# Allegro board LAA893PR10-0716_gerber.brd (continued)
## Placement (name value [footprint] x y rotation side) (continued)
PJP13  PAD-OPEN1x2m  [JUMP_43X79]  239.19 61.34 90 top
PJP14  PAD-OPEN1x1m  [JUMP_43X39]  261.57 66.97 180 top
PJP15  PAD-OPEN1x1m  [JUMP_43X39]  269.97 39.03 180 top
PJP16  PAD-OPEN1x1m  [JUMP_43X39]  247.71 19.89 90 top
PJP18  PAD-OPEN1x3m  [JUMP_43X118]  196.83 47.73 180 top
PJP19  PAD-OPEN1x1m  [JUMP_43X39]  224.6 64.42 0 top
PJP20  PAD-OPEN1x1m  [JUMP_43X39]  238.82 54.66 180 top
PJP21  PAD-OPEN1x3m  [JUMP_43X118]  221.54 38.42 90 top
PJP22  PAD-OPEN1x3m  [JUMP_43X118]  214.85 33.83 0 top
PJP23  PAD-OPEN1x1m  [JUMP_43X39]  153.84 80.74 270 top
PJP26  PAD-OPEN1x2m  [JUMP_43X79]  277.88 24.87 0 top
PJP29  PAD-OPEN1x1m  [JUMP_43X39]  104.14 90.41 180 top
PJP35  PAD-OPEN1x1m  [JUMP_43X39]  164.23 81.29 0 top
PJP36  PAD-OPEN1x3m  [JUMP_43X118]  156.89 86.17 270 top
PJP100  PAD-OPEN 1x3m  [JUMP_43X118]  214.89 63.04 0 bottom
PJP101  PAD-OPEN 1x3m  [JUMP_43X118]  208.38 44.96 270 top
PJP102  PAD-OPEN 1x3m  [JUMP_43X118]  227.72 49.7 0 top
PJP200  PAD-OPEN 1x2m~D  [JUMP_43X79]  60.09 23.35 0 top
PJP201  PAD-OPEN1x1m  [JUMP_43X39]  72.07 15.9 90 top
PJP202  PAD-OPEN1x1m  [JUMP_43X39]  70.98 14.07 0 bottom
PJP203  JUMP_1x3m  [JUMP_43X118]  85.02 27.39 0 top
PJP204  JUMP_1x3m  [JUMP_43X118]  85.02 22.18 0 top
PJP300  -  [JUMP_43X118]  202.8 49.24 270 bottom
PJP302  PAD-OPEN 1x2m~D  [JUMP_43X79]  209.51 64.33 90 bottom
PJP400  PAD-OPEN1x1m  [JUMP_43X39]  115.96 77.06 180 bottom
PJP401  PAD-OPEN1x1m  [JUMP_43X39]  107.69 77.01 180 bottom
PJP500  PAD-OPEN 4x4m  [JUMP_43X118-NPM]  94.64 51.92 0 bottom
PJP700  PAD-OPEN 4x4m  [JUMP_43X118-NPM]  69.14 78.86 315 bottom
PJP701  PAD-OPEN1x1m  [JUMP_43X39]  77.4 82.47 270 top
PJPDC1  ACES_50290-0050N-001  [ACES_50290-0050N-001_5P-T]  56.65 92.65 90 bottom
PL1  FBMJ4516HS720NT_2P  [TAIYO_FBMJ4516HS720NT_2P]  60.84 8.99 180 top
PL2  FBMJ4516HS720NT_2P  [TAIYO_FBMJ4516HS720NT_2P]  60.84 11.72 180 top
PL3  BLM15AG102SN1D_2P  [MURAT_BLM15AG102SN1D_2P]  61.43 104.74 270 top
PL4  FBMJ4516HS720NT_2P  [TAIYO_FBMJ4516HS720NT_2P]  63.02 103.99 0 bottom
PL100  1UH +-20% 6.6A 5X5X3 MOLDING  [L_5X5X3_M_2P-NPM]  213.26 63.04 0 bottom
PL101  2.2UH +-20% 7.8A 7X7X3 MOLDING  [PANAS_ETQP3W2R2WFN_2P]  228.37 56.62 0 bottom
PL102  3.3UH +-20% 6.3A 7X7X3 MOLDING  [PANAS_ETQP3W2R2WFN_2P]  215.04 56.62 0 bottom
PL200  1UH +-20% 11A 7X7X3 MOLDING  [PANAS_ETQP3W2R2WFN_2P]  70.99 20.55 0 bottom
PL301  0.68UH +-20% 7.9A 5X5X3 MOLDING  [L_5X5X3_M_2P]  202.93 57.2 270 bottom
PL500  0.15UH_ETQP4LR15AFM_29A_20%  [PANAS_ETQP4LR15AFM_4P]  115.48 50.34 180 bottom
PL501  FBMA-L11-453215800LMA90T_2P  [KC_FBMA-L11-453215800LMA90T_2P]  93.29 51.92 0 bottom
PL700  1UH +-20% 6.6A 5X5X3 MOLDING  [L_5X5X3_M_2P]  71.07 76.93 135 bottom
PL701  3.3UH +-20% PIMB104T-3R3MS 10A  [TOKO_FDVE1040-H-3R3M-P3_2P]  83.75 71.42 180 bottom
PQ2  -  [FDV301N-G_SOT23-3]  68.88 102.81 180 top
PQ3  -  [MMST3904-7-F_SOT323-3]  72.4 102.47 180 top
PQ100  -  [SIS412DN-T1-GE3_POWERPAK8-5]  223.8 57.67 90 top
PQ101  -  [SIS412DN-T1-GE3_POWERPAK8-5]  213.11 59.65 270 top
PQ102  -  [SI7716ADN-T1-GE3_POWERPAK8-5]  222.44 55.84 270 top
PQ103  -  [SI7716ADN-T1-GE3_POWERPAK8-5]  215.99 53.92 90 top
PQ200  -  [SIS412DN-T1-GE3_POWERPAK8-5]  66.7 22.03 0 top
PQ201  -  [SI7716ADN-T1-GE3_POWERPAK8-5]  64.92 20.46 270 top
PQ701  -  [SI4835DDY-T1-E3_SO8]  92.49 76.68 0 bottom
PQ705  -  [AON6970_DFN5X6D-8-7]  68.13 75.32 270 top
PQ708  -  [DCX124EK-7-F_SC74R-6]  68.97 95.81 270 top
PQ709  SIS496EDNT-T1-GE3 1N POWERPAK1212-8  [SI7716ADN-T1-GE3_POWERPAK8-5]  64.15 95.73 0 top
PQ710  -  [SI7716ADN-T1-GE3_POWERPAK8-5]  66.37 93.88 270 top
PQ711  -  [DMN65D8LW-7_SOT323-3]  73.27 90.17 270 top
PR1  1K_0402_5%  [R_0402]  291.64 8.13 270 top
PR2  100K_0402_5%  [R_0402]  51.52 9.8 270 top
PR7  0_0402_5%  [R_0402]  74.27 103.23 270 bottom
PR8  2.2K_0402_5%  [R_0402]  73.31 100.08 90 bottom
PR9  33_0402_5%  [R_0402]  74.27 100.99 270 bottom
PR10  100K_0402_1%  [R_0402]  73.31 102.31 90 bottom
PR11  10K_0402_1%  [R_0402]  66.38 102.76 270 top
PR12  15K_0402_1%  [R_0402]  72.37 103.24 270 bottom
PR16  4.7K_0805_5%  [R_0805]  66.69 105.77 90 bottom
PR100  6.49K_0402_1%  [R_0402]  219 45.5 90 top
PR101  15K_0402_1%  [R_0402]  217.6 46.41 270 top
PR102  10K_0402_1%  [R_0402]  219.88 45.5 90 top
PR103  0_0402_5%  [R0402_0OHM]  219.06 44.93 90 bottom
PR104  10K_0402_1%  [R_0402]  216.71 46.41 270 top
PR105  20K_0402_1%  [R_0402]  220.77 45.5 90 top
PR106  16.9K_0402_1%  [R_0402]  215.82 45.5 90 top
PR107  100K_0402_1%  [R_0402]  222.61 47.02 90 top
PR108  0_0402_5%  [R0402_0OHM]  221.66 47.02 90 top
PR109  2.2_0603_5%  [R_0603]  214.75 50.59 180 top
PR110  2.2_0603_5%  [R_0603]  223.38 50.59 180 top
PR111  4.7_1206_5%  [R_1206]  227.14 54.01 90 top
PR112  4.7_1206_5%  [R_1206]  210.17 58.97 270 top
PR113  0_0402_5%  [R0402_0OHM]  213.59 46.02 0 top
PR114  200_0402_1%  [R_0402]  214.94 48.18 180 top
PR200  2.2_0603_5%  [R_0603]  67.24 15.66 270 bottom
PR201  19.6K_0402_1%  [R_0402]  65.66 9.61 90 top
PR202  5.1_0603_5%  [R_0603]  64.07 8.48 0 top
PR203  4.7_1206_5%  [R_1206]  67.56 16.61 180 top
PR204  0_0603_5%  [R0603_0OHM]  62.79 8.99 270 top
PR205  8.06K_0402_1%  [R_0402]  71.93 8.03 90 bottom
PR206  768K_0402_1%  [R_0402]  65.77 7.4 0 bottom
PR207  0_0402_5%  [R0402_0OHM]  69.87 8.1 270 top
PR209  10K_0402_1%  [R_0402]  71.03 7.16 0 bottom
PR210  0_0402_5%  [R0402_0OHM]  71.51 8.99 180 top
PR303  1M_0402_1%  [R_0402]  206.74 59.56 0 top
PR305  4.7_1206_5%  [R_1206]  203.95 57 180 top
PR306  0_0402_5%  [R_0402]  207.58 63.29 180 top
PR307  7.5K_0402_1%  [R_0402]  206.75 59.54 90 bottom
PR308  0_0402_5%  [R_0402]  206.66 62.4 0 top
PR309  1K_0402_5%  [R_0402]  208.94 60.57 90 bottom
PR310  10K_0402_1%  [R_0402]  206.66 61.51 0 bottom
PR312  0_0603_5%  [R0603_0OHM]  203.74 60.96 270 top
PR313  0_0402_5%  [R0402_0OHM]  205.23 59.7 90 top
PR315  100K_0402_1%  [R_0402]  207.66 60.45 180 top
PR400  100K_0402_5%  [R_0402]  116.52 73.07 180 bottom
PR401  47K_0402_5%  [R_0402]  115.62 72.17 270 bottom
PR402  8.66K_0402_1%  [R_0402]  107.17 74.1 270 bottom
PR403  10K_0402_1%  [R_0402]  107.17 72.26 270 bottom
PR500  75_0402_1%  [R_0402]  106.6 62.14 90 bottom
PR501  365K_0402_1%  [R_0402]  103.49 62.2 90 bottom
PR502  75_0402_1%  [R_0402]  102.6 62.2 90 bottom
PR503  681K_0402_1%  [R_0402]  101.71 62.2 90 bottom
PR504  36.5K_0402_1%  [R_0402]  100.82 62.2 90 bottom
PR505  10K_0402_5%  [R_0402]  105.52 64.93 90 bottom
PR506  39K_0402_1%  [R_0402]  104.63 64.93 90 bottom
PR507  150K_0402_1%  [R_0402]  103.74 64.93 90 bottom
PR508  100K_0402_1%  [R_0402]  102.85 64.93 90 bottom
PR509  20K_0402_1%  [R_0402]  101.96 64.93 90 bottom
PR510  39K_0402_5%~N  [R_0402]  106.41 64.93 90 bottom
PR511  10K_0402_5%  [R_0402]  107.49 62.14 90 bottom
PR512  2.15K_0402_1%  [R_0402]  110.13 50.9 180 top
PR513  75_0402_1%  [R_0402]  100.14 65.7 180 top
PR514  20K_0402_1%  [R_0402]  110.14 51.84 0 top
PR515  3.01K_0402_1%  [R_0402]  110.14 52.79 0 top
PR516  1.91K_0402_1%  [R_0402]  100.14 67.51 180 top
PR517  2.2_0603_5%  [R_0603]  97.2 57.07 0 bottom
PR518  2M_0402_1%  [R_0402]  107.5 60.17 180 top
PR519  1_0603_5%  [R_0603]  100.12 68.56 180 top
PR520  0_0402_5%  [R0402_0OHM]  99.22 64.76 0 top
PR521  4.87K_0402_1%  [R_0402]  107.68 71.69 270 top
PR522  4.7_1206_5%  [R_1206]  103.93 52.75 270 bottom
PR523  10K_0402_5%  [R_0402]  109.53 70.66 180 top
PR524  2M_0402_1%  [R_0402]  105.65 59.22 90 top
PR525  27K_0402_1%  [R_0402]  106.59 59.22 0 top
PR526  10_0603_1%  [R_0603]  104 72.56 270 top
PR527  54.9_0402_1%  [R_0402]  101.52 72.75 270 top
PR528  75_0402_1%  [R_0402]  100.63 72.75 270 top
PR529  110_0402_1%  [R_0402]  99.74 72.75 270 top
PR531  0_0402_5%  [R0402_0OHM]  109.53 68.75 180 top
PR532  0_0402_5%  [R0402_0OHM]  109.53 67.86 180 top
PR534  0_0402_5%  [R0402_0OHM]  102.92 70.84 90 top
PR535  4.75K_0402_1%  [R_0402]  109.52 71.53 90 top
PR536  0_0402_5%  [R0402_0OHM]  100.14 63.88 180 top
PR539  0_0402_5%  [R0402_0OHM]  100.14 66.59 180 top
PR701  0.01_1206_1%  [R_1206_4P-D]  68.51 85.23 90 bottom
PR703  100_0402_1%  [R_0402]  78.69 90.25 180 bottom
PR704  0_0402_5%  [R0402_0OHM]  78.66 88.42 90 bottom
PR705  0_0402_5%  [R0402_0OHM]  77.77 88.42 90 bottom
PR708  10_1206_5%  [R_1206]  74.33 88.08 270 bottom
PR709  1M_0402_1%  [R_0402]  73.53 92.28 0 top
PR710  34K_0402_1%  [R_0402]  80.58 87.36 180 top
PR711  6.49K_0402_1%  [R_0402]  80.57 85.78 270 top
PR712  2.2_0603_5%  [R_0603]  74.6 82.6 180 bottom
PR713  100K_0402_1%  [R_0402]  77.71 77.7 0 bottom
PR714  0_0402_5%  [R0402_0OHM]  80.12 88.45 270 bottom
PR715  154K_0402_1%  [R_0402]  81.79 80.99 90 top
PR716  0_0402_5%  [R0402_0OHM]  81.07 88.45 270 bottom
PR717  0_0402_5%  [R0402_0OHM]  84.66 83.16 180 bottom
PR718  0_0402_5%  [R0402_0OHM]  84.66 84.94 180 bottom
PR720  0_0402_5%  [R0402_0OHM]  84.66 84.05 180 bottom
PR721  0.01_1206_1%  [R_1206_4P-D]  88.25 69.05 180 top
PR722  4.02K_0402_1%  [R_0402]  79.88 78.66 270 bottom
PR723  10_0603_1%  [R_0603]  81.02 78.66 270 bottom
PR725  1K_0402_5%  [R_0402]  77.71 78.65 0 bottom
PR726  4.7_1206_5%  [R_1206]  72.73 77.3 180 top
PR728  0_0402_5%  [R0402_0OHM]  82.31 77.9 90 bottom
PR729  154K_0402_1%  [R_0402]  80.83 80.99 90 top
PR730  4.02K_0402_1%  [R_0402]  72.55 96.61 0 top
PR731  4.02K_0402_1%  [R_0402]  74.36 97.52 270 top
PR737  4.7_0402_1%  [R_0402]  67.62 95.49 90 top
PR788  20K_0402_1%  [R_0402]  82.42 82.96 0 top
PR799  10K_0402_1%  [R_0402]  76.82 78.61 270 bottom
PRP2  100_0804_8P4R_5%  [RP_0804_8P4R]  53.03 7.72 90 top
PT1  PAD~D  [TPC12]  263.14 34.9 180 bottom
PT2  PAD~D  [TPC12]  261.38 35.29 180 bottom
PU100  -  [TPS51285BRUKR_QFN20_3X3]  217.48 48.03 0 top
PU200  -  [RT8207MZQW_WQFN20_3X3]  69.16 11.39 270 bottom
PU300  SYX198DQNC QFN 10P PWM  [SY8208DQNC_QFN10_3X3]  205.3 60.01 90 bottom
PU400  -  [APL5930KAI-TRG_SO8]  108.84 71.29 90 bottom
PU500  TPS51624RSM QFN 32P VCORE IC  [TPS51622RSM_QFN32_4X4]  102.51 68.43 270 top
PU501  -  [CSD97374CQ4M_SON8_3P5X4P5]  103.71 57.59 270 bottom
PU700  BQ24777RUYR WQFN 28P CHARGER  [BQ24715URUYR_WQFN28_4X4]  78.43 85.21 270 bottom
QA1  -  [L2N7002WT1G_SC-70-3]  38.4 23.73 90 top
QA2  -  [DMN66D0LDW-7_SOT363-6]  27.23 26.92 270 top
QC1  -  [DMN66D0LDW-7_SOT363-6]  187.45 52.62 270 top
QD1  -  [L2N7002WT1G_SC-70-3]  151.84 22.82 0 top
QE2  -  [DMN66D0LDW-7_SOT363-6]  250.68 46.92 90 top
QE3  MMBT3904WT1G_SC70-3~D  [MMBT3904WT1G_SC70-3]  148.35 62.58 270 top
QE4  MMBT3904WT1G_SC70-3~D  [MMBT3904WT1G_SC70-3]  251.32 35.97 180 top
QE5  MMBT3904WT1G_SC70-3~D  [MMBT3904WT1G_SC70-3]  152.13 21.44 270 bottom
QE6  MMBT3904WT1G_SC70-3~D  [MMBT3904WT1G_SC70-3]  101.49 46.25 270 top
QE7  MMBT3904WT1G_SC70-3~D  [MMBT3904WT1G_SC70-3]  237.44 37.93 270 bottom
QL1  -  [DMN66D0LDW-7_SOT363-6]  281.15 80.82 0 top
QL2  -  [DMN66D0LDW-7_SOT363-6]  282.45 79.67 180 top
QN1  -  [DMN66D0LDW-7_SOT363-6]  277.18 10.14 180 bottom
QV1  -  [AO6405_TSOP6]  109.77 94.01 90 bottom
QV2  -  [L2N7002WT1G_SC-70-3]  109.1 98.07 90 bottom
QV7  -  [L2N7002WT1G_SC-70-3]  117.47 80.68 90 top
QV8  -  [LP2301ALT1G_SOT23-3]  118.79 86.3 180 top
QV501  -  [L2N7002WT1G_SC-70-3]  286.32 79.16 0 bottom
QV502  -  [L2N7002WT1G_SC-70-3]  281.79 77.01 270 bottom
QZ1  -  [LP2301ALT1G_SOT23-3]  112.54 86.21 270 top
QZ2  -  [DMN66D0LDW-7_SOT363-6]  242.35 35.8 0 top
QZ3  -  [DMN66D0LDW-7_SOT363-6]  271.61 19.1 270 top
QZ4  -  [DDTA114EUA-7-F_SOT323-3]  275.69 18.71 0 top
QZ6  -  [SI3456DDV-T1-GE3_TSOP6]  166.03 85.9 180 top
QZ7  -  [DMN66D0LDW-7_SOT363-6]  288.59 81.12 90 top
QZ9  -  [DDTA114EUA-7-F_SOT323-3]  284.73 79.6 0 top
QZ10  -  [DMN66D0LDW-7_SOT363-6]  145.52 88.12 270 top
RA1  10K_0402_5%  [R_0402]  20.58 15.7 180 bottom
RA2  100K_0402_5%  [R_0402]  21.69 17.64 270 bottom
RA3  0_0603_5%  [R0603_0OHM]  30.17 12.19 0 top
RA4  0_0603_5%  [R0603_0OHM]  27.43 8.74 90 top
RA5  2.2K_0402_5%  [R_0402]  27.34 19.18 270 top
RA6  2.2K_0402_5%  [R_0402]  26.02 17.37 90 top
RA7  24.9_0402_1%  [R_0402]  24.04 13.17 180 top
RA8  24.9_0402_1%  [R_0402]  24.04 15.86 180 top
RA9  33_0402_5%  [R_0402]  42.14 18.9 180 top
RA12  1K_0402_5%  [R_0402]  40.74 22.02 0 top
RA13  1K_0402_5%  [R_0402]  40.74 21.06 0 top
RA14  33_0402_5%  [R_0402]  38.9 13.95 0 top
RA17  33_0402_5%  [R_0402]  39 17.06 0 top
RA18  10K_0402_5%  [R_0402]  38.91 12.1 90 top
RA21  100K_0402_5%  [R_0402]  30.21 27.05 270 top
RA24  4.7K_0402_5%  [R_0402]  23.12 14.06 0 top
RA25  4.7K_0402_5%  [R_0402]  23.12 14.97 0 top
RA35  0_0402_5%  [R0402_0OHM]  32.81 20.8 0 bottom
RA36  0_0402_5%  [R0402_0OHM]  28.53 11.16 270 bottom
RA37  0_0402_5%  [R0402_0OHM]  33.26 27.09 0 bottom
RA39  0_0805_5%  [R0805_0OHM]  37.03 8.94 180 top
RA40  33_0402_5%  [R_0402]  39.85 13.07 0 top
RA44  100K_0402_5%  [R_0402]  31.52 23.11 90 top
RA45  0_0402_5%  [R0402_0OHM]  30.59 23.11 90 top
RC1  330K_0402_5%  [R_0402]  169.66 45.88 90 bottom
RC2  1K_0402_5%  [R_0402]  290.17 10.6 270 bottom
RC4  0_0402_5%  [R0402_0OHM]  181.18 45.58 0 bottom
RC7  10M_0402_5%  [R_0402]  183.08 45.58 0 bottom
RC8  20K_0402_5%  [R_0402]  186.76 45.83 270 bottom
RC9  1M_0402_5%  [R_0402]  172.07 45.88 90 bottom
RC10  20K_0402_5%  [R_0402]  185.81 45.83 270 bottom
RC11  1K_0402_5%  [R_0402]  165.8 43.71 90 top
RC14  51_0402_5%  [R_0402]  139.86 60.88 0 top
RC15  51_0402_5%  [R_0402]  139.86 63.55 0 top
RC16  51_0402_5%  [R_0402]  139.86 62.66 0 top
RC17  3.01K_0402_1%  [R_0402]  159.88 80.11 90 bottom
RC18  1K_0402_1%  [R_0402]  139.86 61.77 0 top
RC19  33_0402_5%  [R_0402]  154.97 40.49 0 bottom
RC20  33_0402_5%  [R_0402]  154.97 41.57 0 bottom
RC21  51_0402_5%  [R_0402]  127.48 58.4 0 bottom
RC22  33_0402_5%  [R_0402]  154.97 38.59 0 bottom
RC23  33_0402_5%  [R_0402]  154.97 39.54 0 bottom
RC25  1K_0402_5%  [R_0402]  128.63 82.73 270 bottom
RC26  0_0402_5%  [R0402_0OHM]  193.85 51.85 90 top
RC27  0_0402_5%  [R_0402]  194.82 51.85 90 top
RC29  1K_0402_5%  [R_0402]  189.73 64.24 180 top
RC31  1K_0402_5%  [R_0402]  188.72 59.48 180 top
RC33  499_0402_1%  [R_0402]  180.06 59.29 0 bottom
RC34  499_0402_1%  [R_0402]  180.06 58.4 0 bottom
RC35  0_0402_5%  [R0402_0OHM]  188.83 66.99 270 bottom
RC38  33_0402_5%  [R_0402]  188.83 63.98 90 bottom
RC50  0_0402_5%  [R0402_0OHM]  187.94 54.46 0 bottom
RC55  33_0402_5%  [R_0402]  187.94 53 0 bottom
RC61  33_0402_5%  [R_0402]  195.89 59.33 270 bottom
RC62  33_0402_5%  [R_0402]  195.89 63.7 90 bottom
RC63  1M_0402_5%  [R_0402]  154.81 81.01 180 bottom
RC65  0_0402_5%  [R0402_0OHM]  155.17 80.06 0 bottom
RC66  10K_0402_5%  [R_0402]  178.49 62.55 180 top
RC67  22_0402_5%  [R_0402]  161.68 42.89 0 top
RC68  10K_0402_5%  [R_0402]  174.98 66.46 180 bottom
RC69  3.01K_0402_1%  [R_0402]  152.26 80.04 90 bottom
RC74  22_0402_5%  [R_0402]  160.83 42.89 180 top
RC77  0_0402_5%  [R0402_0OHM]  186.53 73.53 270 top
RC78  330K_0402_5%  [R_0402]  171.12 46.79 270 bottom
RC79  10K_0402_5%  [R_0402]  171.24 45.88 90 top
RC80  8.2K_0402_5%  [R_0402]  184.72 75.04 180 top
RC81  10K_0402_5%  [R_0402]  176.96 58.97 180 top
RC82  10K_0402_5%  [R_0402]  176.96 59.85 180 top
RC88  0_0402_5%  [R0402_0OHM]  191.18 74.6 180 top
RC89  0_0402_5%  [R0402_0OHM]  191.18 73.45 180 top
RC91  10K_0402_5%  [R_0402]  167.07 46.08 90 top
RC92  10K_0402_5%  [R_0402]  175.85 46.29 0 top
RC95  8.2K_0402_5%  [R_0402]  186.56 75.04 180 top
RC98  0_0402_5%  [R_0402]  93.53 58.08 180 bottom
RC99  0_0402_5%  [R_0402]  93.53 56.18 180 bottom
RC102  1K_0402_5%  [R_0402]  76.01 52.11 270 top
RC103  1K_0402_5%  [R_0402]  75.09 51.19 90 top
RC106  1K_0402_5%  [R_0402]  87.12 50.02 180 top
RC109  0_0402_5%  [R_0402]  86.79 57.78 270 bottom
RC112  0_0402_5%  [R_0402]  92.62 59.99 0 bottom
RC113  1K_0402_5%  [R_0402]  86.27 46.08 0 top
RC114  49.9_0402_1%  [R_0402]  127.63 68.34 90 bottom
RC115  0_0402_5%  [R_0402]  92.62 59.04 0 bottom
RC116  62_0402_5%  [R_0402]  125.79 68.33 180 bottom
RC117  51_0402_5%  [R_0402]  87.12 47.23 180 top
RC118  0_0402_5%  [R_0402]  92.62 57.13 0 bottom
RC119  0_0402_5%  [R_0402]  75.92 45.88 90 top
RC120  1K_0402_5%  [R_0402]  75.93 47.71 180 top
RC121  56_0402_5%  [R_0402]  124.88 69.58 0 bottom
RC122  1K_0402_5%  [R_0402]  87.12 48.18 180 top
RC123  10K_0402_5%  [R_0402]  131.02 77.99 0 bottom
RC124  51_0402_5%  [R_0402]  127.56 80.96 270 bottom
RC125  51_0402_5%  [R_0402]  127.56 82.2 90 bottom
RC126  51_0402_5%  [R_0402]  126.6 82.2 90 bottom
RC127  51_0402_5%  [R_0402]  126.6 80.96 270 bottom
RC128  51_0402_5%  [R_0402]  75.92 43.97 90 top
RC129  51_0402_5%  [R_0402]  86.79 59.68 270 bottom
RC130  200_0402_1%  [R_0402]  129.98 46.96 270 top
RC131  121_0402_1%  [R_0402]  130.87 46.96 270 top
RC132  100_0402_1%  [R_0402]  129.09 46.96 270 top
RC133  24.9_0402_1%  [R_0402]  158.02 68.57 180 top
RC136  0_0402_5%  [R_0402]  174.85 61.34 0 top
RC139  100K_0402_5%  [R_0402]  167.88 78.99 270 top
RC140  1K_0402_5%  [R_0402]  177.39 65.89 0 top
RC141  100K_0402_5%  [R_0402]  171.18 81.02 270 bottom
RC142  100K_0402_5%  [R_0402]  166.62 81 270 bottom
RC149  3.01K_0402_1%  [R_0402]  151.38 80.06 180 bottom
RC152  22.6_0402_1%  [R_0402]  161.21 56.42 90 top
RC153  10K_0402_5%  [R_0402]  174.99 46.22 270 top
RC155  100K_0402_5%  [R_0402]  176.93 63.08 0 bottom
RC156  100K_0402_5%  [R_0402]  176.08 65.89 180 top
RC158  100K_0402_5%  [R_0402]  174.94 68.9 180 bottom
RC160  100K_0402_5%  [R_0402]  174.94 68.02 180 bottom
RC161  0_0402_5%  [R0402_0OHM]  128.63 80.96 270 bottom
RC163  10K_0402_5%  [R_0402]  170.9 79.01 270 top
RC164  20K_0402_5%  [R_0402]  172.79 79 270 top
RC171  10K_0402_5%  [R_0402]  175.15 63.08 0 bottom
RC174  100K_0402_5%  [R_0402]  183.93 54.08 0 top
RC175  100K_0402_5%  [R_0402]  183.93 53.14 0 top
RC176  1K_0402_5%  [R_0402]  169.9 79 270 top
RC178  49.9_0402_1%  [R_0402]  164.21 46.98 270 bottom
RC179  1K_0402_5%  [R_0402]  178.49 61.34 180 top
RC180  1K_0402_5%  [R_0402]  178.49 63.44 180 top
RC183  1K_0402_1%  [R_0402]  128.39 60.88 180 bottom
RC184  1K_0402_1%  [R_0402]  128.39 61.77 180 bottom
RC185  49.9_0402_1%  [R_0402]  126.55 62.25 90 bottom
RC186  8.2K_0402_1%  [R_0402]  158.92 81.02 270 bottom
RC187  49.9_0402_1%  [R_0402]  163.32 46.98 270 bottom
RC188  1K_0402_1%  [R_0402]  128.39 62.66 180 bottom
RC189  1K_0402_1%  [R_0402]  128.39 64.43 180 bottom
RC190  1K_0402_1%  [R_0402]  128.39 63.55 180 bottom
RC191  1K_0402_5%  [R_0402]  122.67 46.86 270 top
RC192  0_0402_5%  [R_0402]  169.22 80.11 0 bottom
RC193  0_0402_5%  [R_0402]  129.92 78.08 270 bottom
RC194  0_0402_5%  [R_0402]  175.92 46.98 180 bottom
RC195  0_0402_5%  [R_0402]  129.65 46.96 0 bottom
RC196  0_0603_5%  [R_0603]  131.24 80.12 90 bottom
RC197  150_0402_5%  [R_0402]  125.69 80.06 0 top
RC198  10K_0402_5%  [R_0402]  127.45 80.06 0 top
RC199  10K_0402_5%  [R_0402]  129.97 82.73 270 bottom
RC201  1.5K_0402_5%  [R_0402]  129.97 80.96 270 bottom
RC202  1K_0402_5%  [R_0402]  140.07 86.91 0 top
RC204  75_0402_1%  [R_0402]  126.68 68.35 270 bottom
RC207  43_0402_5%  [R_0402]  128.64 66.55 180 bottom
RC208  110_0402_1%  [R_0402]  128.62 68.34 270 bottom
RC209  100_0402_1%  [R_0402]  130.81 77.96 180 top
RC211  5.11_0402_1%  [R_0402]  158.35 58.46 0 top
RC212  0_0402_5%  [R0402_0OHM]  172.12 45.87 90 top
RC213  0_0402_5%  [R_0402]  174.09 45.3 90 top
RC216  0_0402_5%  [R_0402]  174.09 43.42 0 top
RC217  0_0402_5%  [R0402_0OHM]  174.09 44.37 0 top
RC218  100_0402_1%  [R_0402]  129.03 77.96 180 top
RC224  0_0402_5%  [R_0402]  179.75 81.02 270 top
RC225  0_0402_5%  [R_0402]  180.77 81.02 270 top
RC226  0_0402_5%  [R_0402]  181.78 81.02 270 top
RC227  0_0402_5%  [R_0402]  182.8 81.02 270 top
RC228  0_0402_5%  [R_0402]  183.82 81.02 270 top
RC229  0_0402_5%  [R_0402]  184.83 81.02 270 top
RC230  0_0402_5%  [R_0402]  185.85 81.02 270 top
RC231  0_0402_5%  [R_0402]  186.86 80.11 90 top
RC240  10K_0402_5%  [R_0402]  146.59 80.4 90 bottom
RC241  10K_0402_5%  [R_0402]  147.48 80.4 90 bottom
RC242  10K_0402_5%  [R_0402]  164.83 46.98 270 top
RC243  10K_0402_5%  [R_0402]  165.78 46.98 270 top
RC245  100K_0402_5%  [R_0402]  170.35 46.79 270 top
RC247  10K_0402_5%  [R_0402]  184.85 52.22 180 top
RC300  10K_0402_5%  [R_0402]  161.57 63.74 0 top
RC301  0_0402_5%  [R_0402]  288.74 10.17 90 bottom
RC302  1K_0402_5%  [R_0402]  183.91 52.23 270 bottom
RC303  1K_0402_5%  [R_0402]  184.85 51.32 90 bottom
RC304  100K_0402_5%  [R_0402]  189.38 74.6 180 top
RC305  1K_0402_5%  [R_0402]  76.05 55.82 180 top
RC306  10K_0402_5%  [R_0402]  171.83 78.09 90 top
RD2  470_0402_5%  [R_0402]  91.15 9.45 90 top
RD4  1.8K_0402_1%  [R_0402]  80.45 15.29 180 top
RD5  2_0402_1%  [R_0402]  79.54 16.24 0 top
RD6  1.8K_0402_1%  [R_0402]  78.61 17.19 180 top
RD7  24.9_0402_1%  [R_0402]  79.94 18.06 90 top
RD9  220K_0402_5%  [R_0402]  149.97 20.67 90 top
RD10  66.5_0402_1%  [R_0402]  118.68 10.62 180 top
RD11  66.5_0402_1%  [R_0402]  118.68 9.74 180 top
RD12  66.5_0402_1%  [R_0402]  200.6 8.09 180 top
RD13  66.5_0402_1%  [R_0402]  200.6 7.2 180 top
RD14  2M_0402_5%  [R_0402]  149.02 20.67 90 top
RD15  0_0402_5%  [R0402_0OHM]  140.38 16.38 270 top
RD16  0_0402_5%  [R0402_0OHM]  139.43 16.38 270 top
RD18  1.8K_0402_1%  [R_0402]  198.6 13.06 0 top
RD19  2_0402_1%  [R_0402]  200.44 13.06 0 top
RD20  1.8K_0402_1%  [R_0402]  200.06 12.17 0 top
RD21  24.9_0402_1%  [R_0402]  203.2 12.11 180 top
RD22  1.8K_0402_1%  [R_0402]  160.91 18.27 180 top
RD23  2_0402_1%  [R_0402]  159 18.27 180 top
RD24  1.8K_0402_1%  [R_0402]  159.99 17.32 0 top
RD25  24.9_0402_1%  [R_0402]  159 16.36 180 top
RD27  0_0402_5%  [R0402_0OHM]  222.1 17.09 270 top
RD28  0_0402_5%  [R0402_0OHM]  220.09 18.91 270 top
RE8  100K_0402_5%  [R_0402]  254.89 59.65 90 top
RE11  100K_0402_5%  [R_0402]  252.41 59.65 90 top
RE20  100K_0402_5%  [R_0402]  114.87 96.25 180 bottom
RE21  10K_0402_5%  [R_0402]  253.43 59.65 90 top
RE24  10K_0402_5%  [R_0402]  252.92 70.57 90 top
RE25  100K_0402_5%  [R_0402]  250.68 54.86 0 top
RE26  10_0402_5%  [R_0402]  250.68 55.75 0 top
RE31  100K_0402_5%  [R_0402]  267.78 53.7 270 top
RE32  0_0402_5%  [R0402_0OHM]  267.78 51.76 270 top
RE33  10K_0402_5%  [R_0402]  266.89 52.79 90 top
RE35  10K_0402_5%  [R_0402]  253.97 32.5 270 top
RE36  100K_0402_5%  [R_0402]  257.79 53.21 270 top
RE37  2.2K_0402_5%  [R_0402]  267.9 40.39 180 top
RE43  2.2K_0402_5%  [R_0402]  267.9 41.28 180 top
RE48  10K_0402_5%  [R_0402]  248.71 41.16 90 top
RE51  10K_0402_5%  [R_0402]  247.14 45.62 270 top
RE55  100K_0402_5%  [R_0402]  249.79 41.16 90 top
RE56  10K_0402_5%  [R_0402]  255.18 34.18 0 top
RE57  1K_0402_5%  [R_0402]  270.1 43.16 0 top
RE58  100K_0402_5%  [R_0402]  269.16 43.17 270 top
RE60  43_0402_5%  [R_0402]  264.02 34.79 270 top
RE61  0_0402_5%  [R0402_0OHM]  266.81 46.73 270 top
RE63  100K_0402_5%  [R_0402]  256.08 29.77 90 top
RE64  4.7K_0402_5%  [R_0402]  270.1 42.21 0 top
RE65  100_0402_1%  [R_0402]  258.34 30.1 0 top
RE66  10_0402_5%  [R_0402]  251.34 39.09 180 top
RE67  10K_0402_5%  [R_0402]  249.36 49.43 0 top
RE68  100K_0402_5%  [R_0402]  247.79 48.49 270 top
RE69  8.2K_0402_5%  [R_0402]  250.42 37.19 0 top
RE70  2.2K_0402_5%  [R_0402]  249.44 36.3 0 top
RE71  49.9_0402_1%  [R_0402]  300.35 41.43 180 top
RE72  10K_0402_5%  [R_0402]  300.87 37.5 180 top
RE73  10K_0402_5%  [R_0402]  300.87 35.28 180 top
RE75  100K_0402_5%  [R_0402]  300.87 36.36 180 top
RE77  1.58K_0402_1%  [R_0402]  251.33 44.88 180 top
RE78  1K_0402_5%  [R_0402]  251.33 40.11 180 top
RE79  1K_0402_5%  [R_0402]  258.75 53.21 270 top
RE81  10K_0402_5%  [R_0402]  266.86 49.11 270 top
RE82  10K_0402_5%  [R_0402]  267.75 49.11 270 top
RE83  100K_0402_5%  [R_0402]  261.27 65.26 180 top
RE84  100K_0402_5%  [R_0402]  256.83 60.58 270 top
RE86  10K_0402_5%  [R_0402]  258.32 33.81 90 top
RE87  10K_0402_5%  [R_0402]  254.44 71.49 270 top
RE88  47K_0402_5%  [R_0402]  260.16 32.88 90 top
RE91  0_0402_5%  [R_0402]  256.98 54.97 180 top
RE100  0_0402_5%  [R0402_0OHM]  251.58 51 90 top
RE101  0_0402_5%  [R0402_0OHM]  250.68 51 90 top
RE274  0_0402_5%  [R_0402]  184.83 51.29 180 top
RE275  0_0402_5%  [R0402_0OHM]  255.84 59.66 90 top
RE278  0_0402_5%  [R_0402]  251.65 48.21 90 top
RE279  0_0402_5%  [R0402_0OHM]  170.34 43.15 0 top
RE280  0_0402_5%  [R_0402]  170.36 45.04 270 top
RE281  0_0402_5%  [R_0402]  167.07 44.63 270 top
RE282  0_0402_5%  [R0402_0OHM]  168.08 44.63 270 top
RE283  0_0402_5%  [R_0402]  263.1 49.19 90 bottom
RI13  10K_0402_5%  [R_0402]  288.59 38.86 0 top
RI14  22.1K_0402_1%  [R_0402]  284.57 41.88 270 top
RL1  10K_0402_5%  [R_0402]  262.57 87.02 180 top
RL2  10K_0402_5%  [R_0402]  262.57 88.91 180 top
RL3  0_0402_5%  [R0402_0OHM]  254.35 86.13 180 bottom
RL4  4.7K_0402_5%  [R_0402]  253.22 91.17 90 top
RL5  10K_0402_5%  [R_0402]  251.08 92.09 270 top
RL6  4.7K_0402_5%  [R_0402]  252.11 92.09 270 top
RL7  0_0402_5%  [R0402_0OHM]  252.12 90.25 180 top
RL8  0_0603_5%  [R0603_0OHM]  249.97 92.04 270 top
RL9  10K_0402_5%  [R_0402]  252.11 89.33 180 top
RL10  0_0402_5%  [R0402_0OHM]  249.02 84.44 0 top
RL11  1M_0402_5%  [R_0402]  250.87 84.45 270 top
RL12  1K_0402_5%  [R_0402]  261.66 85.91 0 top
RL13  3.01K_0402_1%  [R_0402]  251.82 82.61 270 top
RL14  150_0402_5%  [R_0402]  283 83.79 90 top
RL15  75_0402_1%  [R_0402]  267.99 90.18 90 top
RL16  75_0402_1%  [R_0402]  269.26 90.18 90 top
RL17  75_0402_1%  [R_0402]  275.61 90.18 90 top
RL18  75_0402_1%  [R_0402]  276.88 90.18 90 top
RL19  150_0402_5%  [R_0402]  283.89 83.79 90 top
RL20  150_0402_5%  [R_0402]  284.78 83.79 90 top
RL21  5.6_0603_5%  [R_0603]  252.59 80.44 270 top
RL22  5.6_0603_5%  [R_0603]  253.79 80.44 270 top
RL23  5.6_0603_5%  [R_0603]  255.06 80.44 270 top
RL24  5.6_0603_5%  [R_0603]  256.27 80.44 270 top
RL25  5.6_0603_5%  [R_0603]  257.54 80.44 270 top
RL26  5.6_0603_5%  [R_0603]  258.75 80.44 270 top
RL27  5.6_0603_5%  [R_0603]  260.02 80.44 270 top
RL28  5.6_0603_5%  [R_0603]  261.22 80.44 270 top
RL29  1M_0402_5%  [R_0402]  279.92 80.73 90 top
RL30  1M_0402_5%  [R_0402]  279.92 79.69 270 top
RN1  100K_0402_5%  [R_0402]  272.32 10.08 0 bottom
RN2  100K_0402_5%  [R_0402]  276.53 14.03 270 bottom
RN3  2.2K_0402_5%  [R_0402]  279.05 4.36 0 bottom
RN4  2.2K_0402_5%  [R_0402]  281.81 4.36 180 bottom
RN5  10K_0402_5%  [R_0402]  268.33 10.98 270 bottom
RN6  10K_0402_5%  [R_0402]  250.14 19.09 270 top
RN7  10K_0402_5%  [R_0402]  251.04 18.17 270 top
RN8  4.7K_0402_5%  [R_0402]  260.36 16.31 180 top
RN9  4.7K_0402_5%  [R_0402]  259.45 17.2 0 top
RN10  4.7K_0402_5%  [R_0402]  260.36 18.97 180 top
RN11  4.7K_0402_5%  [R_0402]  259.45 18.08 0 top
RN12  4.7K_0402_5%  [R_0402]  267.7 17.94 0 top
RN13  4.7K_0402_5%  [R_0402]  268.62 17.06 180 top
RN14  4.7K_0402_5%  [R_0402]  268.62 19.79 180 top
RN16  4.7K_0402_5%  [R_0402]  268.62 18.9 180 top
RN18  4.7K_0402_5%  [R_0402]  259.45 19.86 0 top
RN19  7.87K_0402_1%  [R_0402]  259.45 20.76 0 top
RN20  4.7K_0402_5%  [R_0402]  268.62 15.28 180 top
RN21  4.7K_0402_5%  [R_0402]  268.62 16.17 180 top
RN22  4.7K_0402_5%  [R_0402]  259.62 11.26 0 top
RN23  4.7K_0402_5%  [R_0402]  262.3 11.27 180 top
RN24  4.7K_0402_5%  [R_0402]  269.99 20.66 270 top
RN25  4.7K_0402_5%  [R_0402]  269.99 18.87 270 top
RPC1  10K_8P4R_5%  [RP_0804_8P4R]  176.31 43.85 90 top
RPC2  2.2K_0804_8P4R_5%  [RP_0804_8P4R]  165.2 80.56 90 bottom
RPC3  10K_8P4R_5%  [RP_0804_8P4R]  180.13 68.93 0 top
RPC4  10K_8P4R_5%  [RP_0804_8P4R]  177.8 67.42 180 top
RPC5  10K_8P4R_5%  [RP_0804_8P4R]  185.28 58.86 180 top
RPC6  10K_8P4R_5%  [RP_0804_8P4R]  179.94 64.38 0 bottom
RPC7  10K_8P4R_5%  [RP_0804_8P4R]  184.39 58.26 180 bottom
RPC8  10K_8P4R_5%  [RP_0804_8P4R]  179.94 67.18 0 bottom
RPC9  10K_8P4R_5%  [RP_0804_8P4R]  181.28 64.57 180 top
RPC10  10K_8P4R_5%  [RP_0804_8P4R]  185.28 55.94 180 top
RPC11  33_0804_8P4R_5%  [RP_0804_8P4R]  187.81 62.14 0 top
RPC12  33_0804_8P4R_5%  [RP_0804_8P4R]  187.81 56.23 0 top
RPC14  2.2K_0804_8P4R_5%  [RP_0804_8P4R]  183.24 60 0 bottom
RPC15  10K_8P4R_5%  [RP_0804_8P4R]  180.32 63.08 0 top
RPC16  10K_8P4R_5%  [RP_0804_8P4R]  184.14 67.43 180 top
RPC17  10K_8P4R_5%  [RP_0804_8P4R]  177.91 68.68 180 bottom
RPC18  10K_8P4R_5%  [RP_0804_8P4R]  177.91 65.88 180 bottom
RPC19  10K_8P4R_5%  [RP_0804_8P4R]  177.6 58.85 0 bottom
RPC20  100K_0804_8P4R_5%  [RP_0804_8P4R]  169.48 82.02 90 bottom
RPE3  2.2K_0804_8P4R_5%  [RP_0804_8P4R]  260.35 51.73 90 top
RPE5  100K_0804_8P4R_5%  [RP_0804_8P4R]  263.27 51.73 90 top
RPE6  10K_8P4R_5%  [RP_0804_8P4R]  262.73 34.15 270 top
RPE7  10K_8P4R_5%  [RP_0804_8P4R]  299.85 40.15 0 top
RPE9  100K_0804_8P4R_5%  [RP_0804_8P4R]  256.68 70.96 90 top
RPE10  100K_0804_8P4R_5%  [RP_0804_8P4R]  253.56 52.18 90 top
RR1  10_0402_5%  [R_0402]  283.89 35.97 90 top
RR2  191_0402_1%  [R_0402]  278.56 32.74 0 top
RR3  0_0402_5%  [R0402_0OHM]  282.57 35.97 90 top
RR4  0_0402_5%  [R0402_0OHM]  281.68 35.97 90 top
RR5  4.7K_0402_1%  [R_0402]  289.7 28.26 0 top
RR6  100K_0402_5%  [R_0402]  283.16 24.15 90 top
RR8  100K_0402_5%  [R_0402]  284.1 25.07 270 top
RR11  1M_0402_5%  [R_0402]  275.46 27.08 270 top
RR15  10K_0402_5%  [R_0402]  281.8 26.33 0 top
RV1  4.7K_0402_5%  [R_0402]  109.98 89.39 180 top
RV2  4.7K_0402_5%  [R_0402]  107.22 89.39 0 top
RV3  100K_0402_5%  [R_0402]  100.54 93.52 270 top
RV4  270K_0402_5%  [R_0402]  112.1 98.14 180 bottom
RV5  47K_0402_5%  [R_0402]  110.25 97.24 90 bottom
RV6  47K_0402_5%  [R_0402]  118.37 82.46 180 top
RV7  2.2K_0402_5%  [R_0402]  223.78 95.61 180 top
RV8  10K_0402_5%  [R_0402]  219.44 94.52 90 top
RV9  2.2K_0402_5%  [R_0402]  220.96 95.61 0 top
RV50  4.99K_0402_1%  [R_0402]  221.64 84.73 180 bottom
RV51  4.7K_0402_5%  [R_0402]  232.88 85.18 180 bottom
RV52  4.7K_0402_5%  [R_0402]  231.97 86.09 0 bottom
RV54  4.7K_0402_5%  [R_0402]  222.45 88.12 270 bottom
RV55  4.7K_0402_5%  [R_0402]  220.69 81.7 0 top
RV56  4.7K_0402_5%  [R_0402]  220.68 80.76 0 top
RV57  4.7K_0402_5%  [R_0402]  233.47 79.12 180 bottom
RV58  4.7K_0402_5%  [R_0402]  226.41 75.77 90 top
RV60  4.7K_0402_5%  [R_0402]  228.81 75.77 90 top
RV61  4.7K_0402_5%  [R_0402]  223.39 87.22 90 bottom
RV62  4.7K_0402_5%  [R_0402]  222.83 81.7 0 top
RV63  4.7K_0402_5%  [R_0402]  232.56 80.02 0 bottom
RV64  4.7K_0402_5%  [R_0402]  222.83 80.5 0 top
RV65  4.7K_0402_5%  [R_0402]  226.42 78.02 90 top
RV66  4.7K_0402_5%  [R_0402]  228.82 78.02 90 top
RV67  1M_0402_5%  [R_0402]  230.79 88.12 270 bottom
RV68  100K_0402_5%  [R_0402]  225.21 75.77 90 top
RV501  100K_0402_5%  [R_0402]  287.33 73.08 270 bottom
RV502  100K_0402_5%  [R_0402]  287.33 70.38 90 bottom
RV503  5.1M_0402_5%  [R_0402]  286.43 76.03 0 bottom
RV504  1M_0402_5%  [R_0402]  287.35 76.92 180 bottom
RV505  100K_0402_5%  [R_0402]  286.43 77.94 0 bottom
RV507  100K_0402_5%  [R_0402]  279.56 74.47 0 bottom
RV510  4.7K_0402_5%  [R_0402]  231.97 83.35 0 bottom
RV511  4.7K_0402_5%  [R_0402]  232.88 84.24 180 bottom
RV514  100K_0402_5%  [R_0402]  233.47 77.11 180 bottom
RV515  100K_0402_5%  [R_0402]  233.47 78.24 180 bottom
RZ5  100K_0402_5%  [R_0402]  144.44 87.76 270 top
RZ8  2.2K_0402_5%  [R_0402]  251.51 13.37 0 top
RZ9  2.2K_0402_5%  [R_0402]  254.26 13.37 180 top
RZ10  1M_0402_5%  [R_0402]  259.43 13.31 180 top
RZ14  100K_0402_5%  [R_0402]  241.59 34.72 0 top
RZ15  100K_0402_5%  [R_0402]  244.34 34.72 180 top
RZ16  100K_0402_5%  [R_0402]  148.54 88.25 270 top
RZ17  0_0402_5%  [R0402_0OHM]  197.94 87.25 270 top
RZ18  4.7K_0402_5%  [R_0402]  247.7 22 90 top
RZ19  4.7K_0402_5%  [R_0402]  246.81 22 90 top
RZ21  33_0402_5%  [R_0402]  269.12 37.3 0 top
RZ22  10K_0402_5%  [R_0402]  267.98 34.55 180 top
RZ24  10K_0402_5%  [R_0402]  272.53 24.35 90 top
RZ25  390_0402_5%  [R_0402]  271.26 16.31 270 top
RZ26  33_0402_5%  [R_0402]  199.72 87.25 270 top
RZ27  110_0402_1%  [R_0402]  275.5 17.5 0 top
RZ28  330_0402_5%  [R_0402]  270.3 16.31 270 top
RZ29  33_0402_5%  [R_0402]  197.05 87.25 270 top
RZ30  33_0402_5%  [R_0402]  194.5 87.22 270 top
RZ31  100K_0402_5%  [R_0402]  288.6 79.99 180 top
RZ32  150_0402_5%  [R_0402]  287.46 83.45 0 top
RZ33  110_0402_1%  [R_0402]  284.78 78.4 0 top
RZ34  110_0402_1%  [R_0402]  285.62 82.4 180 top
RZ35  33_0402_5%  [R_0402]  198.83 87.25 270 top
RZ38  100K_0402_5%  [R_0402]  251.29 30.85 180 top
RZ41  0_0402_5%  [R_0402]  221.47 68.9 90 top
RZ42  0_0402_5%  [R0402_0OHM]  222.4 68.9 90 top
RZ44  0.01_1206_1%  [R_1206]  200.11 43.13 270 top
RZ46  0_0603_5%  [R_0603]  224.6 62.17 0 top
RZ51  0_0402_5%  [R0402_0OHM]  265.88 31.48 180 top
RZ56  0_0402_5%  [R_0402]  244.28 32.33 0 top
RZ57  0_0402_5%  [R0402_0OHM]  245.2 31.43 180 top
SW1  SS3-CMFTQR9_3P  [SW_SS3-CMFTQR9_3P]  297.13 6.17 180 bottom
SW3  SKRBAAE010_4P  [SW_SKRBAAE010_4P]  294.16 86 270 top
T8  PAD~D  [TPC12]  169.35 46.58 0 top
T9  PAD~D  [TPC12]  253.15 35.69 90 top
T10  PAD~D  [TPC12]  129.12 71.03 180 bottom
T11  PAD~D  [TPC12]  127.75 70.66 180 bottom
T12  PAD~D  [TPC12]  135.7 68.21 0 top
T13  PAD~D  [TPC12]  128 72.71 180 bottom
T14  PAD~D  [TPC12]  133.8 66.93 0 top
T15  PAD~D  [TPC12]  132.42 69.19 0 top
T16  PAD~D  [TPC12]  173.77 60.69 0 top
T21  PAD~D  [TPC12]  168.37 57.61 0 top
T22  PAD~D  [TPC12]  169.49 62.48 0 top
T27  PAD~D  [TPC12]  173.61 57.7 180 bottom
T28  PAD~D  [TPC12]  128.36 47.43 180 bottom
T29  PAD~D  [TPC12]  128.79 49.22 180 bottom
T30  PAD~D  [TPC12]  128.98 74.45 180 bottom
T31  PAD~D  [TPC12]  128.99 75.95 180 bottom
T32  PAD~D  [TPC12]  249.86 61.49 0 top
T33  PAD~D  [TPC12]  140.82 76.35 180 bottom
T34  PAD~D  [TPC12]  141.89 77.27 180 bottom
T35  PAD~D  [TPC12]  129.87 66 180 bottom
T74  PAD~D  [TPC12]  128.51 65.35 180 bottom
T75  PAD~D  [TPC12]  126.26 65.07 180 bottom
T76  PAD~D  [TPC12]  135.53 66.36 0 top
T77  PAD~D  [TPC12]  134.11 65.48 0 top
T88  PAD~D  [TPC12]  260.75 86.54 180 top
T89  PAD~D  [TPC12]  261.96 87.97 180 top
T96  PAD~D  [TPC12]  254.37 72.72 180 top
T97  PAD~D  [TPC12]  250.97 71.28 180 top
T98  PAD~D  [TPC12]  249.3 65.66 180 top
T109  PAD~D  [TPC12]  168.97 77 0 top
TL1  NS692417  [MHPC_NS692417_24P]  279.42 81.51 180 bottom
UA1  -  [ALC3235-CG_MQFN48_6X6]  36.31 15.37 90 top
UC1  BDW-ULT-DDR3L_BGA1168  [BDW-ULT-DDR3L_BGA_1168P-T]  170.78 73.51 0 bottom
UC2  -  [W25Q64FVSSIQ_SO8]  190.61 68.5 0 bottom
UC3  -  [W25Q32FVSSIQ_SO8]  194.42 51.54 180 bottom
UC4  -  [74AHC1G09GW_TSSOP5]  185.23 73.58 180 top
UC5  TC7SH08FU_SSOP5~D  [TC7SH08FU_SSOP5]  187.81 71.46 0 top
UC6  TC7SH08FU_SSOP5~D  [TC7SH08FU_SSOP5]  190.78 52.63 270 top
UC7  -  [74CBTLV3126BQ_DHVQFN14_2P5X3]  90.03 59.31 270 bottom
UC8  -  [74AUP1G07GW_TSSOP5]  136.89 88.32 270 top
UD1  -  [74AUP1G07GW_TSSOP5]  146.15 19.79 0 top
UE2  -  [MEC5085-LZY_DQFN132_11X11]  262.69 47.91 180 top
UE3  ECE1099-FZG_QFN40_6X6~D  [ECE1099-FZG_QFN40_6X6]  251.21 68.01 270 top
UI1  SY6288D10CAC_MSOP8  [G547I2P81U_MSOP8]  91.7 84.21 270 bottom
UI2  SY6288D10CAC_MSOP8  [G547I2P81U_MSOP8]  255.09 92.9 270 bottom
UI3  -  [TPS2544RTER_WQFN16_3X3]  286.76 40.41 0 top
UL1  WGI218LM-QQ89-B0_QFN48_6X6~D  [WGI217LM-QPN9-A2_QFN48_6X6]  253.65 87.99 270 top
UL2  TC7SH08FU_SSOP5~D  [TC7SH08FU_SSOP5]  261.23 83.75 270 top
UN1  LNG3DMTR_LGA16_3X3~D  [LNG3DMTR_LGA16_3X3]  280.67 8.35 270 bottom
UN2  -  [PI3EQX6741STZDEX_TQFN20_4X4]  265.04 19.67 180 top
UN3  TPS22967DSGR_SON8_2X2~D  [TPS22965DSGR_SON8_2X2]  252.44 20.12 270 top
UR1  OZ777FJ2LN-B1_QFN48_6X6  [OZ777FJ2LN_QFN48_6X6]  281.67 33.11 270 top
UV2  -  [AP2330W-7_SC59-3]  225.01 93.76 90 bottom
UV7  -  [PS8339BQFN56GTR2-A0_QFN56_7X7]  229.22 78.23 180 bottom
UV24  -  [AP2821KTR-G1_SOT23-5]  101.79 88.81 90 top
UV501  AP2337SA-7 SOT-23  [AP2330W-7_SC59-3]  286.19 64.81 0 bottom
UV502  PI3C3125LEX_TSSOP14~D  [PI3C3125LEX_TSSOP14]  279.99 68.76 90 bottom
UZ1  AT97SC3205-X3A15-ABF_TSSOP28~D  [AT97SC3205_TSSOP28]  194.16 78.56 0 top
UZ2  APE8990GN3B_SON14_2X3  [TPS22966DPUR_SON14_2X3]  242.75 56.82 90 top
UZ3  TPS22967DSGR_SON8_2X2~D  [TPS22965DSGR_SON8_2X2]  248.73 29.3 90 top
UZ5  -  [RT9818A-44GU3_SC70-3]  268.83 36.32 270 top
UZ6  TC7SH08FU_SSOP5~D  [TC7SH08FU_SSOP5]  267.22 33.45 270 top
UZ8  APE8990GN3B_SON14_2X3  [TPS22966DPUR_SON14_2X3]  223.14 67.16 180 top
UZ9  APE8990GN3B_SON14_2X3  [TPS22966DPUR_SON14_2X3]  218.29 42.92 180 top
UZ10  TC7SH08FU_SSOP5~D  [TC7SH08FU_SSOP5]  264.03 58.72 180 top
UZ11  -  [TC7SH08FU_SSOP5]  247.5 33.8 180 top
YC1  32.768KHZ_12.5PF_9H03220008  [Y_9H03220008_2P]  182.07 48.49 0 bottom
YC2  24MHZ_12PF_X3G024000DC1H  [Y_X3G024000DC1H_4P]  155.67 82.28 180 bottom
YE1  32.768KHZ_12.5PF_Q13FC135000040  [Y_Q13FC135000040_2P]  269.35 44.39 90 top
YL1  25MHZ_18PF_7V25000034  [Y_7V25000034_4P]  249.49 80.48 90 top

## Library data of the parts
CA1-CA6 CA8 CA11-CA13 CA17 CA19 CA22-CA24 CA27 CA28 CA30 CA33 CA35 CA41 CA45 CA47 CA50 CA54 CC1-CC13 CC17 CC20-CC22 CC24-CC28 CC35 CC37 CC40 CC43 CC44 CC49 CC50 CC52 CC57-CC59 CC61 CC65 CC66 CC68-CC73 CC78 CC80 CC82 CC83 CC95-CC97 CC100 CD1-CD11 CD21-CD27 CD30-CD44 CD54-CD60 CD63 CD64 CE2 CE3 CE8 CE10-CE20 CE22-CE30 CE34-CE40 CE46 CI3-CI5 CI7 CI10 CI12 CI13 CI16 CI17 CI19 CI27 CI28 CL1-CL3 CL5 CL6 CL8-CL11 CL13-CL15 CL18 CL19 CN2-CN4 CN13-CN20 CN23-CN26 CN29 CN30 CR2-CR4 CR6 CR8 CR10 CR13 CR15 CR17 CR19 CR21-CR27 CR31 CR35 CV1-CV6 CV10 CV11 CV23 CV26 CV60-CV62 CV66 CV69 CV71-CV80 CV145-CV150 CV152 CV153 CV156 CV157 CV501-CV510 CV512-CV514 CZ1 CZ2 CZ4-CZ7 CZ9 CZ13-CZ18 CZ20-CZ23 CZ25 CZ30 CZ31 CZ34-CZ37 CZ39-CZ48 CZ50 CZ64 PC3 PC20 PC105 PC203 PC212-PC215 PC300 PC304 PC400 PC402 PC403 PC501-PC504 PC506 PC511-PC514 PC520 PC702 PC703 PC711 PC713 PC718 PC719 PC726-PC728 PC730 = C_0402
CA9 CA10 CA16 CA18 CA25 CA26 CA29 CA31 CA43 CA44 CA46 CA48 CA49 CA51-CA53 CC23 CC29-CC34 CC36 CC47 CC51 CC55 CC56 CC60 CC63 CC64 CC79 CC84 CC85 CD12-CD19 CD28 CD29 CD45-CD52 CD61 CD62 CE1 CE21 CE31 CE32 CI6 CI11 CL4 CL7 CL12 CL16 CL17 CL20 CL21 CN1 CR1 CR7 CR9 CR14 CR18 CR34 CV9 CV12 CV27 CZ19 CZ38 PC1 PC9 PC100 PC109-PC111 PC114 PC117-PC119 PC204 PC208 PC209 PC211 PC301 PC302 PC309 PC310 PC500 PC505 PC507-PC510 PC701 PC710 PC712 PC721 PC722 PC729 PC731 = C_0603
CC39 CD20 CD53 PC207 PC966 = C_D2
CC41 CC42 = C_D3
CC67 CC77 CC81 CI1 CI8 CI14 = C_1206
CL22 = C_1808
CMOS1 = SHORTPADS-S: User Part Number: PART#
DA1-DA3 DA6 DA7 = L03ESDL5V0CC3-2_SOT23-3
DA4 DA5 DE1 DZ1-DZ4 = RB751S40T1G_SOD523-2
DI1 DI4 DI6 = L05ESDL5V0NA-4_SLP2510P8-10-9
DI2 DI3 DI5 DV4 PD5 = AZC199-02SPR7G_SOT23-3
DV1-DV3 = BAT54CW_SOT323-3
FD1-FD4 = FIDUCIAL_C40M80
H1-H4 H6 H7 H9-H11 H13 H21 = H_2P3
H5 = H_5P5N
H12 = H_3P6
H14-H17 = H_3P5
H18 = H_5P2X2P6N
H19 = H_3P2
H22 = H_3P3
H23 = H_2P6N
JAPS1 = ACES_50506-01841-P01_18P
JDEG1 JLPDE1 = HB_A531015-SCHR21_10P
JDIMM1 = LCN_DAN06-K4406-0103_204P
JDIMM2 = LCN_DAN06-K4406-0103_204P-S
JEDP1 = ACES_50398-04041-001_40P
JFAN1 = ACES_50271-0040N-001_4P
JHDMI1 = CONCR_099BKAC19YBLCNF_19P-T
JHP1 = SINGA_2SJ3080-039111F_6P-T
JKBTP1 = E-T_6705K-Y16N-00L_16P
JLED1 = E-T_6705K-Y10N-00L_10P-T
JLOM1 = SANTA_130456-511_13P-T
JMDP1 = ACON_MAR2B-20K1803_20P-T
JNGFF1 = BELLW_80148-3221_67P-T
JRTC1 = TYCO_2-1775293-2_2P
JSATA1 = STARC_115B20-000000-G2-R_20P-T
JSD1 = T-SOL_156-2000302608_19P_NR-S
JSPI1 = E-T_6700K-Y20N-00L_20P
JSPK1 = ACES_50279-0040N-001_4P
JTAG1 = SHORTPADS: User Part Number: PART#
JUSB1 JUSB2 = C-K_26210-8K1A-02_9P-T
JUSB3 = SINGA_2UB1641-000111F_9P-T
JXDP1 = SAMTE_BSH-030-01-L-D-A_60P
LA2 LA3 = MURAT_BLM15BD601SN1D_2P
LA5 = MURAT_BLM15PX600SN1D_2P
LA6-LA11 = MURAT_BLM15PX330SN1D_2P
LC1-LC5 = MURAT_LQM2MPN2R2NG0L_2P
LED3 = LED_LTW-193ZDS5_2P
LI1-LI9 LV3 LV6 LV10 LV12 LV27 LZ1 = MURAT_DLW21HN900HQ2L_4P
LL1 = TAIYO_BRC2012T4R7MD_2P
LV1 = MURAT_BLM15BB221SN1D_2P
MIC1 = KNOW_SPM1437HM4H-6_6P
PBATT1 = DEREN_40-42251-01001RHF_10P-T
PC21 PC22 PC101 PC102 PC200 PC201 PC205 PC303 PC305-PC308 PC401 PC404 PC515-PC518 PC704-PC709 PC714-PC717 PC723-PC725 PC734 PC900-PC904 PC913-PC917 = C_0805
PC113 PC115 = C_APXK6R3ARA221MF451
PC519 = C_D
PD1 PD2 = TVNST52302AB0_SOT523-3
PD3 = BAS40CW_SOT323-3
PD703 = PDS5100H-13_POWERDI5-3
PD704 PD705 = SDMK0340L-7-F_SOD323-2
PH500 PH501 PR1 PR2 PR7-PR12 PR100-PR102 PR104-PR107 PR114 PR201 PR205 PR206 PR209 PR303 PR306-PR310 PR315 PR400-PR403 PR500-PR516 PR518 PR521 PR523-PR525 PR527-PR529 PR535 PR703 PR709-PR711 PR713 PR715 PR722 PR725 PR729-PR731 PR737 PR788 PR799 RA1 RA2 RA5-RA9 RA12-RA14 RA17 RA18 RA21 RA24 RA25 RA40 RA44 RC1 RC2 RC7-RC11 RC14-RC23 RC25 RC27 RC29 RC31 RC33 RC34 RC38 RC55 RC61-RC63 RC66-RC69 RC74 RC78-RC82 RC91 RC92 RC95 RC98 RC99 RC102 RC103 RC106 RC109 RC112-RC133 RC136 RC139-RC142 RC149 RC152 RC153 RC155 RC156 RC158 RC160 RC163 RC164 RC171 RC174-RC176 RC178-RC180 RC183-RC195 RC197-RC199 RC201 RC202 RC204 RC207-RC209 RC211 RC213 RC216 RC218 RC224-RC231 RC240-RC243 RC245 RC247 RC300-RC306 RD2 RD4-RD7 RD9-RD14 RD18-RD25 RE8 RE11 RE20 RE21 RE24-RE26 RE31 RE33 RE35-RE37 RE43 RE48 RE51 RE55-RE58 RE60 RE63-RE73 RE75 RE77-RE79 RE81-RE84 RE86-RE88 RE91 RE274 RE278 RE280 RE281 RE283 RI13 RI14 RL1 RL2 RL4-RL6 RL9 RL11-RL20 RL29 RL30 RN1-RN14 RN16 RN18-RN25 RR1 RR2 RR5 RR6 RR8 RR11 RR15 RV1-RV9 RV50-RV52 RV54-RV58 RV60-RV68 RV501-RV505 RV507 RV510 RV511 RV514 RV515 RZ5 RZ8-RZ10 RZ14-RZ16 RZ18 RZ19 RZ21 RZ22 RZ24-RZ35 RZ38 RZ41 RZ56 = R_0402
PJP1 PJP18 PJP21 PJP22 PJP36 PJP100-PJP102 PJP203 PJP204 PJP300 = JUMP_43X118
PJP4 PJP5 PJP7 PJP10-PJP12 PJP14-PJP16 PJP19 PJP20 PJP23 PJP29 PJP35 PJP201 PJP202 PJP400 PJP401 PJP701 = JUMP_43X39
PJP6 PJP9 PJP13 PJP26 PJP200 PJP302 = JUMP_43X79
PJP500 PJP700 = JUMP_43X118-NPM
PJPDC1 = ACES_50290-0050N-001_5P-T
PL1 PL2 PL4 = TAIYO_FBMJ4516HS720NT_2P
PL3 = MURAT_BLM15AG102SN1D_2P
PL100 = L_5X5X3_M_2P-NPM
PL101 PL102 PL200 = PANAS_ETQP3W2R2WFN_2P
PL301 PL700 = L_5X5X3_M_2P
PL500 = PANAS_ETQP4LR15AFM_4P
PL501 = KC_FBMA-L11-453215800LMA90T_2P
PL701 = TOKO_FDVE1040-H-3R3M-P3_2P
PQ2 = FDV301N-G_SOT23-3
PQ3 = MMST3904-7-F_SOT323-3
PQ100 PQ101 PQ200 = SIS412DN-T1-GE3_POWERPAK8-5
PQ102 PQ103 PQ201 PQ709 PQ710 = SI7716ADN-T1-GE3_POWERPAK8-5
PQ701 = SI4835DDY-T1-E3_SO8
PQ705 = AON6970_DFN5X6D-8-7
PQ708 = DCX124EK-7-F_SC74R-6
PQ711 = DMN65D8LW-7_SOT323-3
PR16 = R_0805
PR103 PR108 PR113 PR207 PR210 PR313 PR520 PR531 PR532 PR534 PR536 PR539 PR704 PR705 PR714 PR716-PR718 PR720 PR728 RA35-RA37 RA45 RC4 RC26 RC35 RC50 RC65 RC77 RC88 RC89 RC161 RC212 RC217 RD15 RD16 RD27 RD28 RE32 RE61 RE100 RE101 RE275 RE279 RE282 RL3 RL7 RL10 RR3 RR4 RZ17 RZ42 RZ51 RZ57 = R0402_0OHM
PR109 PR110 PR200 PR202 PR517 PR519 PR526 PR712 PR723 RC196 RL21-RL28 RZ46 = R_0603
PR111 PR112 PR203 PR305 PR522 PR708 PR726 RZ44 = R_1206
PR204 PR312 RA3 RA4 RL8 = R0603_0OHM
PR701 PR721 = R_1206_4P-D
PRP2 RPC1-RPC12 RPC14-RPC20 RPE3 RPE5-RPE7 RPE9 RPE10 = RP_0804_8P4R
PT1 PT2 T8-T16 T21 T22 T27-T35 T74-T77 T88 T89 T96-T98 T109 = TPC12
PU100 = TPS51285BRUKR_QFN20_3X3
PU200 = RT8207MZQW_WQFN20_3X3
PU300 = SY8208DQNC_QFN10_3X3
PU400 = APL5930KAI-TRG_SO8
PU500 = TPS51622RSM_QFN32_4X4
PU501 = CSD97374CQ4M_SON8_3P5X4P5
PU700 = BQ24715URUYR_WQFN28_4X4
QA1 QD1 QV2 QV7 QV501 QV502 = L2N7002WT1G_SC-70-3
QA2 QC1 QE2 QL1 QL2 QN1 QZ2 QZ3 QZ7 QZ10 = DMN66D0LDW-7_SOT363-6
QE3-QE7 = MMBT3904WT1G_SC70-3
QV1 = AO6405_TSOP6
QV8 QZ1 = LP2301ALT1G_SOT23-3
QZ4 QZ9 = DDTA114EUA-7-F_SOT323-3
QZ6 = SI3456DDV-T1-GE3_TSOP6
RA39 = R0805_0OHM
SW1 = SW_SS3-CMFTQR9_3P
SW3 = SW_SKRBAAE010_4P
TL1 = MHPC_NS692417_24P
UA1 = ALC3235-CG_MQFN48_6X6
UC1 = BDW-ULT-DDR3L_BGA_1168P-T
UC2 = W25Q64FVSSIQ_SO8
UC3 = W25Q32FVSSIQ_SO8
UC4 = 74AHC1G09GW_TSSOP5
UC5 UC6 UL2 UZ6 UZ10 UZ11 = TC7SH08FU_SSOP5
UC7 = 74CBTLV3126BQ_DHVQFN14_2P5X3
UC8 UD1 = 74AUP1G07GW_TSSOP5
UE2 = MEC5085-LZY_DQFN132_11X11
UE3 = ECE1099-FZG_QFN40_6X6
UI1 UI2 = G547I2P81U_MSOP8
UI3 = TPS2544RTER_WQFN16_3X3
UL1 = WGI217LM-QPN9-A2_QFN48_6X6
UN1 = LNG3DMTR_LGA16_3X3
UN2 = PI3EQX6741STZDEX_TQFN20_4X4
UN3 UZ3 = TPS22965DSGR_SON8_2X2
UR1 = OZ777FJ2LN_QFN48_6X6
UV2 UV501 = AP2330W-7_SC59-3
UV7 = PS8339BQFN56GTR2-A0_QFN56_7X7
UV24 = AP2821KTR-G1_SOT23-5
UV502 = PI3C3125LEX_TSSOP14
UZ1 = AT97SC3205_TSSOP28
UZ2 UZ8 UZ9 = TPS22966DPUR_SON14_2X3
UZ5 = RT9818A-44GU3_SC70-3
YC1 = Y_9H03220008_2P
YC2 = Y_X3G024000DC1H_4P
YE1 = Y_Q13FC135000040_2P
YL1 = Y_7V25000034_4P

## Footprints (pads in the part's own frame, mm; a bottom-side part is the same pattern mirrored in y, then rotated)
74AHC1G09GW_TSSOP5
  oval 0.381x1.346 smd: 1(0,0) 2(0.65,0) 3(1.3,0) 4(1.3,1.79) 5(0,1.79)
74AUP1G07GW_TSSOP5
  oval 0.381x1.346 smd: 1(0,0) 2(0.65,0) 3(1.3,0) 4(1.3,1.79) 5(0,1.79)
74CBTLV3126BQ_DHVQFN14_2P5X3
  oval 1.041x0.254 smd: 1(0,0) 7(2.95,0) 8(2.95,0.5) 14(0,0.5)
  oval 0.254x1.041 smd: 2(0.475,-0.975) 3(0.975,-0.975) 4(1.475,-0.975) 5(1.975,-0.975) 6(2.475,-0.975) 9(2.475,1.475) 10(1.975,1.475) 11(1.475,1.475) 12(0.975,1.475) 13(0.475,1.475)
  rect 1.499x0.991 smd: 15(1.475,0.25)
ACES_50271-0040N-001_4P
  oval 0.787x1.6 smd: 1(0,0) 2(-1.25,0) 3(-2.5,0) 4(-3.75,0)
  rect 2.108x2.997 smd: 5(2.55,-2.9) 6(-6.3,-2.9)
ACES_50279-0040N-001_4P
  oval 0.787x1.905 smd: 1(0,0) 2(1.25,0) 3(2.5,0) 4(3.75,0)
  rect 1.295x3.353 smd: 5(6.6,-4.925) 6(-2.85,-4.925)
ACES_50290-0050N-001_5P-T
  rect 0.838x7.01 smd: 1(0,0) 2(1.5,0) 3(3,0) 4(4.5,0) 5(6,0)
ACES_50398-04041-001_40P
  oval 0.254x1.295 smd: 1(0,0) 2(0.5,0) 3(1,0) 4(1.5,0) 5(2,0) 6(2.5,0) 7(3,0) 8(3.5,0) 9(4,0) 10(4.5,0) 11(5,0) 12(5.5,0) 13(6,0) 14(6.5,0) 15(7,0) 16(7.5,0) 17(8,0) 18(8.5,0) 19(9,0) 20(9.5,0) 21(10,0) 22(10.5,0) 23(11,0) 24(11.5,0) 25(12,0) 26(12.5,0) 27(13,0) 28(13.5,0) 29(14,0) 30(14.5,0) 31(15,0) 32(15.5,0) 33(16,0) 34(16.5,0) 35(17,0) 36(17.5,0) 37(18,0) 38(18.5,0) 39(19,0) 40(19.5,0)
  rect 1.194x3.2 smd: 41(-2.4,1.95) 45(21.9,1.95)
  rect 2.311x1.295 smd: 42(0.85,3.9) 43(9.75,3.9) 44(18.65,3.9)
ACES_50506-01841-P01_18P
  oval 0.305x0.889 smd: 1(0,0) 2(0.5,0) 3(1,0) 4(1.5,0) 5(2,0) 6(2.5,0) 7(3,0) 8(3.5,0) 9(4,0) 10(4.5,0) 11(5,0) 12(5.5,0) 13(6,0) 14(6.5,0) 15(7,0) 16(7.5,0) 17(8,0) 18(8.5,0)
  rect 0.991x2.007 smd: 19(-2.1,-3.05) 20(10.6,-3.05)
ACON_MAR2B-20K1803_20P-T
  round 0.991 hole 0.991 unplated: (-0.825,3.26) (6.825,3.26)
  oval 0.813x0.914 hole 0.61: 1(0,0) 3(0.5,1) 5(1.5,1) 7(2,0) 9(2.5,-1) 11(3.5,-1) 13(4,0) 15(4.5,1) 17(5.5,1) 19(6,0)
  oval 0.356x2.159 smd: 2(0.3,2.985) 4(0.9,2.985) 6(1.5,2.985) 8(2.1,2.985) 10(2.7,2.985) 12(3.3,2.985) 14(3.9,2.985) 16(4.5,2.985) 18(5.1,2.985) 20(5.7,2.985)
  oval 1.092x2.007 hole 0.711x1.6: 21(-2.1,1.66) 23(8.1,1.66)
  oval 1.092x1.803 hole 0.711x1.397: 22(-2.8,-3.04) 24(8.8,-3.04)
ALC3235-CG_MQFN48_6X6
  oval 0.203x0.889 smd: 1(0,0) 2(0.4,0) 3(0.8,0) 4(1.2,0) 5(1.6,0) 6(2,0) 7(2.4,0) 8(2.8,0) 9(3.2,0) 10(3.6,0) 11(4,0) 12(4.4,0) 25(4.4,6.1) 26(4,6.1) 27(3.6,6.1) 28(3.2,6.1) 29(2.8,6.1) 30(2.4,6.1) 31(2,6.1) 32(1.6,6.1) 33(1.2,6.1) 34(0.8,6.1) 35(0.4,6.1) 36(0,6.1)
  oval 0.889x0.203 smd: 13(5.25,0.85) 14(5.25,1.25) 15(5.25,1.65) 16(5.25,2.05) 17(5.25,2.45) 18(5.25,2.85) 19(5.25,3.25) 20(5.25,3.65) 21(5.25,4.05) 22(5.25,4.45) 23(5.25,4.85) 24(5.25,5.25) 37(-0.85,5.25) 38(-0.85,4.85) 39(-0.85,4.45) 40(-0.85,4.05) 41(-0.85,3.65) 42(-0.85,3.25) 43(-0.85,2.85) 44(-0.85,2.45) 45(-0.85,2.05) 46(-0.85,1.65) 47(-0.85,1.25) 48(-0.85,0.85)
  rect 4.394x4.394 smd: 49(2.2,3.05)
AO6405_TSOP6
  oval 0.508x1.473 smd: 1(0,0) 2(0.95,0) 3(1.9,0) 4(1.9,2.35) 5(0.95,2.35) 6(0,2.35)
AON6970_DFN5X6D-8-7
  oval 0.66x0.635 smd: 1(0,0) 3(3.81,5.67) 4(2.54,5.67) 5(1.27,5.67) 6(0,5.67)
  custom 0.485x0.485 smd: 2(1.905,0.655)
  rect 3.988x2.667 smd: 7(1.905,3.62)
AP2330W-7_SC59-3
  oval 0.787x0.991 smd: 1(0,0) 2(-0.95,-2.4) 3(0.95,-2.4)
AP2821KTR-G1_SOT23-5
  oval 0.508x0.787 smd: 1(0,0) 2(0.95,0) 3(1.9,0) 4(1.9,2.4) 5(0,2.4)
APL5930KAI-TRG_SO8
  oval 0.635x1.854 smd: 1(0,0) 2(1.27,0) 3(2.54,0) 4(3.81,0) 5(3.81,5.165) 6(2.54,5.165) 7(1.27,5.165) 8(0,5.165)
  rect 2.87x2.489 smd: 9(1.905,2.582)
AT97SC3205_TSSOP28
  oval 0.381x1.626 smd: 1(0,0) 2(0.65,0) 3(1.3,0) 4(1.95,0) 5(2.6,0) 6(3.25,0) 7(3.9,0) 8(4.55,0) 9(5.2,0) 10(5.85,0) 11(6.5,0) 12(7.15,0) 13(7.8,0) 14(8.45,0) 15(8.45,5.8) 16(7.8,5.8) 17(7.15,5.8) 18(6.5,5.8) 19(5.85,5.8) 20(5.2,5.8) 21(4.55,5.8) 22(3.9,5.8) 23(3.25,5.8) 24(2.6,5.8) 25(1.95,5.8) 26(1.3,5.8) 27(0.65,5.8) 28(0,5.8)
AZC199-02SPR7G_SOT23-3
  oval 1.016x1.524 smd: 1(0,0) 2(0.965,2.083) 3(-0.965,2.083)
BAS40CW_SOT323-3
  oval 0.813x0.914 smd: 1(0,0) 2(0.65,1.6) 3(-0.65,1.6)
BAT54CW_SOT323-3
  oval 0.61x0.559 smd: 1(0,0) 2(-0.65,-1.85) 3(0.65,-1.85)
BDW-ULT-DDR3L_BGA_1168P-T
  round 0.508 smd: A3(-1.137,0) A62(-38.036,0) AW1(0,22.042) AW63(-38.628,22.057) AY2(-0.543,22.628) AY62(-38.062,22.628) B2(-0.508,0.508) B63(-38.628,0.592) C1(0,1.137)
  round 0.381 smd: A4(-1.894,0) A5(-2.554,0) A6(-3.75,0) A59(-35.9,0) A60(-36.726,0) A61(-37.386,0) AA9(-5.032,11.576) AA21(-11.688,11.489) AA23(-13.115,11.489) AA58(-35.377,11.33) AB10(-5.476,12.053) AB20(-11.18,11.896) AB21(-11.688,12.302) AB22(-12.607,11.896) AB23(-13.115,12.302) AB57(-35.057,11.98) AC9(-5.032,12.529) AC20(-11.18,12.709) AC22(-12.607,12.709) AC58(-35.377,12.63) AD10(-5.476,13.005) AD21(-11.688,13.115) AD23(-13.115,13.115) AD57(-35.057,13.28) AE9(-5.032,13.481) AE10(-5.476,13.958) AE20(-11.18,13.521) AE21(-11.688,13.928) AE22(-12.607,13.521) AE23(-13.115,13.928) AE58(-35.377,13.931) AF9(-5.032,14.434) AF11(-6.059,14.282) AF12(-6.872,14.282) AF14(-7.685,14.282) AF15(-8.497,14.282) AF17(-9.31,14.282) AF18(-10.123,14.282) AF20(-10.936,14.282) AF22(-12.607,14.334) AG10(-5.653,14.79) AG11(-6.465,14.79) AG13(-7.278,14.79) AG14(-8.091,14.79) AG16(-8.904,14.79) AG17(-9.717,14.79) AG19(-10.529,14.79) AG20(-11.342,14.79) AG23(-13.115,14.741) AG57(-35.057,14.581) AG58(-35.692,15.009) AH22(-12.607,15.147) AH24(-13.92,15.289) AH26(-15.22,15.289) AH28(-16.521,15.289) AH30(-17.821,15.289) AH32(-19.122,15.289) AH34(-20.422,15.289) AH36(-21.723,15.289) AH38(-23.023,15.289) AH40(-24.324,15.289) AH42(-25.624,15.289) AH44(-26.925,15.289) AH46(-28.225,15.289) AH49(-29.526,15.289) AH51(-30.826,15.289) AH53(-32.127,15.289) AH55(-33.427,15.289) AH57(-34.728,15.289) AJ23(-13.115,15.553) AJ25(-14.57,15.614) AJ27(-15.871,15.614) AJ29(-17.171,15.614) AJ31(-18.472,15.614) AJ33(-19.772,15.614) AJ35(-21.073,15.614) AJ37(-22.373,15.614) AJ39(-23.674,15.614) AJ41(-24.974,15.614) AJ43(-26.275,15.614) AJ45(-27.575,15.614) AJ47(-28.875,15.614) AJ50(-30.176,15.614) AJ52(-31.476,15.614) AJ54(-32.777,15.614) AJ56(-34.077,15.614) AJ58(-35.378,15.614) AT1(0,19.997) AT63(-38.628,19.848) AU1(0,20.657) AU63(-38.628,20.673) AV1(0,21.318) AV2(-0.66,21.308) AV62(-37.978,21.318) AV63(-38.628,21.333) AW2(-0.66,21.968) AW3(-1.321,21.968) AW61(-37.328,21.978) AW62(-37.978,21.978) AY3(-1.267,22.628) AY4(-1.928,22.628) AY5(-2.588,22.628) AY59(-36.088,22.628) AY60(-36.748,22.628) AY61(-37.409,22.628) B3(-1.259,0.65) B61(-37.315,0.66) B62(-37.978,0.724) C2(-0.65,1.259) C62(-37.978,1.384) C63(-38.628,1.316) D1(0,1.861) D63(-38.628,1.976) E1(0,2.522) E23(-13.333,2.601) E25(-14.714,2.601) E27(-15.84,2.601) E29(-17.221,2.601) E31(-18.348,2.601) E33(-19.729,2.601) E35(-20.855,2.601) E37(-22.236,2.601) E39(-23.363,2.601) E41(-24.744,2.601) E43(-25.87,2.601) E45(-27.251,2.601) E47(-28.378,2.601) E49(-29.759,2.601) E51(-30.885,2.601) E53(-32.266,2.601) E55(-33.393,2.601) E57(-34.774,2.601) E63(-38.628,2.647) F1(0,3.436) F22(-12.717,3.058) F24(-14.023,3.126) F26(-15.277,3.126) F28(-16.531,3.126) F30(-17.785,3.126) F32(-19.038,3.126) F34(-20.292,3.126) F36(-21.546,3.126) F38(-22.8,3.126) F40(-24.053,3.126) F42(-25.307,3.126) F44(-26.561,3.126) F46(-27.815,3.126) F48(-29.068,3.126) F50(-30.322,3.126) F52(-31.576,3.126) F54(-32.83,3.126) F56(-34.083,3.126) F58(-35.377,3.126) G22(-12.607,3.768) G23(-13.333,3.451) G25(-14.714,3.451) G27(-15.84,3.451) G29(-17.221,3.451) G31(-18.348,3.451) G33(-19.729,3.451) G35(-20.855,3.451) G37(-22.236,3.451) G39(-23.363,3.451) G41(-24.744,3.451) G43(-25.87,3.451) G45(-27.251,3.451) G47(-28.378,3.451) G49(-29.759,3.451) G51(-30.885,3.451) G53(-32.266,3.451) G55(-33.393,3.451) G57(-34.774,3.451) H22(-12.607,4.581) H23(-13.115,4.174) H57(-35.057,4.101) J22(-12.607,5.393) J23(-13.115,4.987) J58(-35.377,4.827) K9(-5.032,5.861) K10(-5.935,5.7) K12(-6.888,5.7) K14(-7.84,5.7) K16(-8.793,5.7) K18(-9.745,5.7) K19(-10.698,5.7) K21(-11.65,5.7) K23(-13.115,5.8) K57(-35.057,5.478) L10(-5.476,6.338) L11(-6.412,6.144) L13(-7.364,6.144) L15(-8.317,6.144) L17(-9.269,6.144) L18(-10.222,6.144) L20(-11.18,6.206) L22(-12.607,6.206) L58(-35.377,6.128) M9(-5.032,6.814) M20(-11.18,7.019) M21(-11.688,6.613) M22(-12.607,7.019) M23(-13.115,6.613) M57(-35.057,6.778) N10(-5.476,7.29) N21(-11.688,7.425) N23(-13.115,7.425) N58(-35.377,7.428) P9(-5.032,7.766) P20(-11.18,7.832) P22(-12.607,7.832) P57(-35.057,8.078) R10(-5.476,8.243) R20(-11.18,8.645) R21(-11.688,8.238) R22(-12.607,8.645) R23(-13.115,8.238) T9(-5.032,8.719) T21(-11.688,9.051) T23(-13.115,9.051) T58(-35.377,8.729) U9(-5.032,9.671) U10(-5.476,9.195) U20(-11.18,9.457) U22(-12.607,9.457) U57(-35.057,9.379) V10(-5.476,10.148) V21(-11.688,9.864) V23(-13.115,9.864) V58(-35.377,10.029) W9(-5.032,10.624) W20(-11.18,10.27) W21(-11.688,10.677) W22(-12.607,10.27) W23(-13.115,10.677) W57(-35.057,10.679) Y10(-5.476,11.1) Y20(-11.18,11.083) Y22(-12.607,11.083)
  round 0.305 smd: A8(-4.538,0) A9(-5.452,0) A11(-6.367,0) A12(-7.116,0) A14(-8.03,0) A15(-8.945,0) A17(-9.694,0) A18(-10.608,0) A20(-11.523,0) A21(-12.272,0) A23(-13.186,0) A24(-14.023,0.325) A25(-14.714,0) A27(-15.84,0) A28(-16.531,0.325) A29(-17.221,0) A31(-18.348,0) A32(-19.038,0.325) A33(-19.729,0) A35(-20.855,0) A36(-21.546,0.325) A37(-22.236,0) A39(-23.363,0) A40(-24.053,0.325) A41(-24.744,0) A43(-25.87,0) A44(-26.561,0.325) A45(-27.251,0) A47(-28.378,0) A48(-29.068,0.325) A49(-29.759,0) A51(-30.885,0) A52(-31.576,0.325) A53(-32.266,0) A55(-33.393,0) A56(-34.083,0.325) A57(-34.774,0) AA1(0,11.717) AA2(-0.65,11.717) AA3(-1.3,11.678) AA4(-1.951,11.678) AA59(-36.027,11.638) AA60(-36.678,11.638) AA61(-37.328,11.638) AA62(-37.978,11.676) AA63(-38.628,11.676) AB5(-2.637,12.053) AB6(-3.287,12.053) AB7(-3.937,12.053) AB8(-4.587,12.053) AC1(0,12.466) AC2(-0.65,12.466) AC3(-1.3,12.504) AC4(-1.951,12.504) AC59(-36.027,12.464) AC60(-36.678,12.464) AC61(-37.328,12.464) AC62(-37.978,12.426) AC63(-38.628,12.426) AD1(0,13.215) AD2(-0.65,13.215) AD3(-1.3,13.177) AD4(-1.951,13.177) AD5(-2.637,13.005) AD6(-3.287,13.005) AD7(-3.937,13.005) AD8(-4.587,13.005) AD59(-36.027,13.137) AD60(-36.678,13.137) AD61(-37.328,13.137) AD62(-37.978,13.175) AD63(-38.628,13.175) AE5(-2.637,13.958) AE6(-3.287,13.958) AE7(-3.937,13.958) AE8(-4.587,13.958) AE59(-36.027,13.962) AE60(-36.678,13.962) AE61(-37.328,13.962) AE62(-37.978,13.924) AE63(-38.628,13.924) AF1(0,13.964) AF2(-0.65,13.964) AF3(-1.3,14.003) AF4(-1.951,14.003) AG1(0,14.714) AG2(-0.65,14.714) AG3(-1.3,14.676) AG4(-1.951,14.676) AG5(-2.637,14.91) AG6(-3.287,14.91) AG7(-3.937,14.91) AG8(-4.587,14.91) AG21(-11.955,15.122) AG60(-36.352,14.602) AG61(-37.003,14.602) AG62(-37.653,14.602) AG63(-38.303,14.602) AH1(0,15.463) AH2(-0.65,15.463) AH3(-1.3,15.501) AH4(-1.951,15.501) AH10(-5.653,15.476) AH11(-6.465,15.476) AH13(-7.278,15.476) AH14(-8.091,15.476) AH16(-8.904,15.476) AH17(-9.717,15.476) AH19(-10.529,15.476) AH20(-11.342,15.476) AH60(-36.678,15.278) AH61(-37.328,15.278) AH62(-37.978,15.278) AH63(-38.628,15.278) AJ5(-2.637,15.863) AJ6(-3.287,15.863) AJ7(-3.937,15.863) AJ8(-4.587,15.863) AJ10(-5.653,16.126) AJ11(-6.465,16.126) AJ13(-7.278,16.126) AJ14(-8.091,16.126) AJ60(-36.352,15.954) AJ61(-37.003,15.954) AJ62(-37.653,15.954) AJ63(-38.303,15.954) AK1(0,16.212) AK2(-0.65,16.212) AK3(-1.3,16.174) AK4(-1.951,16.174) AK8(-4.303,16.451) AK18(-9.848,16.266) AK20(-10.801,16.266) AK21(-11.753,16.266) AK60(-36.678,16.523) AK61(-37.328,16.523) AK62(-37.978,16.629) AK63(-38.628,16.629) AL1(0,16.962) AL2(-0.65,16.962) AL3(-1.3,17) AL4(-1.951,17) AL5(-2.901,16.776) AL7(-3.739,16.776) AL8(-4.303,17.101) AL10(-5.658,16.776) AL11(-6.221,17.101) AL13(-7.576,16.776) AL15(-8.14,17.101) AL17(-9.222,16.583) AL18(-9.848,16.916) AL20(-10.801,16.916) AL21(-11.753,16.916) AL22(-12.706,16.916) AL23(-13.529,16.916) AL25(-14.504,16.916) AL26(-15.456,16.916) AL28(-16.409,16.916) AL29(-17.361,16.916) AL31(-18.26,16.591) AL32(-18.824,16.916) AL33(-19.726,16.916) AL35(-20.729,16.916) AL36(-21.58,16.916) AL38(-22.634,16.916) AL39(-23.542,16.591) AL40(-24.131,16.916) AL42(-24.944,16.916) AL43(-25.897,16.916) AL45(-26.874,16.916) AL46(-27.802,16.916) AL48(-28.856,16.916) AL49(-29.757,16.916) AL51(-30.761,16.916) AL52(-31.583,16.916) AL54(-32.61,16.916) AL55(-33.562,16.916) AL57(-34.509,16.916) AL58(-35.408,16.916) AL60(-36.352,17.169) AL61(-37.003,17.169) AM1(0,17.711) AM2(-0.65,17.711) AM3(-1.3,17.673) AM4(-1.951,17.673) AM5(-2.901,17.426) AM7(-3.739,17.426) AM8(-4.303,17.752) AM10(-5.658,17.426) AM11(-6.221,17.752) AM13(-7.576,17.426) AM15(-8.14,17.752) AM17(-9.222,17.233) AM18(-9.848,17.567) AM20(-10.801,17.567) AM21(-11.753,17.567) AM22(-12.706,17.567) AM23(-13.529,17.567) AM25(-14.504,17.567) AM26(-15.456,17.567) AM28(-16.409,17.567) AM29(-17.361,17.567) AM31(-18.26,17.242) AM32(-18.824,17.567) AM33(-19.726,17.567) AM35(-20.729,17.567) AM36(-21.58,17.567) AM38(-22.634,17.567) AM40(-24.131,17.567) AM42(-24.944,17.567) AM43(-25.897,17.567) AM45(-26.874,17.567) AM46(-27.802,17.567) AM48(-28.856,17.567) AM49(-29.757,17.567) AM51(-30.761,17.567) AM52(-31.583,17.567) AM54(-32.61,17.567) AM55(-33.562,17.567) AM57(-34.509,17.567) AM58(-35.408,17.567) AM60(-36.678,17.816) AM61(-37.328,17.816) AM62(-37.978,17.709) AM63(-38.628,17.709) AN1(0,18.46) AN2(-0.65,18.46) AN3(-1.3,18.498) AN4(-1.951,18.498) AN5(-2.901,18.077) AN7(-3.739,18.077) AN8(-4.303,18.402) AN10(-5.658,18.077) AN11(-6.221,18.402) AN13(-7.576,18.077) AN15(-8.14,18.402) AN17(-9.222,17.883) AN18(-9.848,18.217) AN20(-10.801,18.217) AN21(-11.753,18.217) AN22(-12.706,18.217) AN23(-13.529,18.217) AN25(-14.504,18.217) AN26(-15.456,18.217) AN28(-16.409,18.217) AN29(-17.361,18.217) AN31(-18.26,17.892) AN32(-18.824,18.217) AN33(-19.726,18.217) AN35(-20.729,18.217) AN36(-21.58,18.217) AN38(-22.634,18.217) AN39(-23.542,17.892) AN40(-24.131,18.217) AN42(-24.944,18.217) AN43(-25.897,18.217) AN45(-26.874,18.217) AN46(-27.802,18.217) AN48(-28.856,18.217) AN49(-29.757,18.217) AN51(-30.761,18.217) AN52(-31.583,18.217) AN54(-32.61,18.217) AN55(-33.562,18.217) AN57(-34.509,18.217) AN58(-35.408,18.217) AN60(-36.352,18.385) AN61(-37.003,18.385) AN62(-37.653,18.385) AN63(-38.303,18.385) AP1(0,19.21) AP2(-0.65,19.21) AP3(-1.3,19.171) AP4(-1.951,19.171) AP5(-2.901,18.727) AP7(-3.739,18.727) AP8(-4.303,19.052) AP10(-5.658,18.727) AP11(-6.221,19.052) AP13(-7.576,18.727) AP15(-8.14,19.052) AP17(-9.222,18.533) AP18(-9.848,18.867) AP20(-10.801,18.867) AP21(-11.753,18.867) AP22(-12.706,18.867) AP23(-13.529,18.867) AP25(-14.504,18.867) AP26(-15.456,18.867) AP28(-16.409,18.867) AP29(-17.361,18.867) AP31(-18.26,18.542) AP32(-18.824,18.867) AP33(-19.726,18.867) AP35(-20.729,18.867) AP36(-21.58,18.867) AP38(-22.634,18.867) AP39(-23.542,18.542) AP40(-24.131,18.867) AP42(-24.944,18.867) AP43(-25.897,18.867) AP45(-26.874,18.867) AP46(-27.802,18.867) AP48(-28.856,18.867) AP49(-29.757,18.867) AP51(-30.761,18.867) AP52(-31.583,18.867) AP54(-32.61,18.867) AP55(-33.562,18.867) AP57(-34.509,18.867) AP58(-35.408,18.867) AP60(-36.678,19.06) AP61(-37.328,19.06) AP62(-37.978,19.06) AP63(-38.628,19.06) AR5(-2.901,19.377) AR7(-3.739,19.377) AR8(-4.303,19.702) AR10(-5.658,19.377) AR11(-6.221,19.702) AR13(-7.576,19.377) AR15(-8.14,19.702) AR17(-9.222,19.184) AR18(-9.848,19.517) AR20(-10.801,19.517) AR21(-11.753,19.517) AR22(-12.706,19.517) AR23(-13.529,19.517) AR25(-14.504,19.517) AR26(-15.456,19.517) AR28(-16.409,19.517) AR29(-17.361,19.517) AR31(-18.26,19.192) AR32(-18.824,19.517) AR33(-19.726,19.517) AR35(-20.729,19.517) AR36(-21.58,19.517) AR38(-22.634,19.517) AR39(-23.542,19.192) AR40(-24.131,19.517) AR42(-24.944,19.517) AR43(-25.897,19.517) AR45(-26.874,19.517) AR46(-27.802,19.517) AR48(-28.856,19.517) AR49(-29.757,19.517) AR51(-30.761,19.517) AR52(-31.583,19.517) AR54(-32.61,19.517) AR55(-33.562,19.517) AR57(-34.509,19.517) AR58(-35.408,19.517) AT2(-0.65,19.959) AT3(-1.3,19.997) AT4(-1.951,19.997) AT5(-2.901,20.027) AT7(-3.739,20.027) AT10(-5.658,20.027) AT13(-7.576,20.027) AT35(-20.437,20.22) AT37(-22.011,20.22) AT40(-23.586,20.22) AT42(-25.161,20.22) AT43(-26.736,20.22) AT46(-28.311,20.22) AT49(-29.912,20.248) AT61(-37.003,19.634) AT62(-37.812,19.69) AU2(-0.655,20.647) AU3(-1.315,20.647) AU4(-1.976,20.647) AU6(-3.337,20.678) AU7(-4.163,20.678) AU8(-4.836,20.678) AU10(-5.661,20.678) AU11(-6.335,20.678) AU12(-7.16,20.678) AU14(-7.833,20.678) AU15(-8.659,20.678) AU16(-9.222,20.353) AU17(-9.86,20.678) AU18(-10.536,20.353) AU19(-11.105,20.678) AU20(-11.751,20.353) AU21(-12.397,20.678) AU22(-12.966,20.353) AU23(-13.642,20.678) AU24(-14.318,20.353) AU25(-14.993,20.678) AU26(-15.669,20.353) AU27(-16.238,20.678) AU28(-16.884,20.353) AU29(-17.531,20.678) AU30(-18.1,20.353) AU31(-18.775,20.678) AU33(-19.372,20.33) AU34(-19.974,20.678) AU35(-20.899,20.678) AU36(-21.549,20.678) AU37(-22.474,20.678) AU39(-23.124,20.678) AU40(-24.048,20.678) AU41(-24.699,20.678) AU42(-25.623,20.678) AU43(-26.274,20.678) AU44(-27.198,20.678) AU46(-27.848,20.678) AU47(-28.773,20.678) AU49(-29.423,20.678) AU50(-30.4,20.678) AU51(-30.98,20.353) AU52(-31.656,20.678) AU53(-32.331,20.353) AU54(-32.9,20.678) AU55(-33.547,20.353) AU56(-34.193,20.678) AU57(-34.762,20.353) AU58(-35.438,20.678) AU59(-36.002,20.353) AU60(-36.566,20.678) AU61(-37.277,20.401) AU62(-37.978,20.663) AV3(-1.321,21.308) AV4(-1.976,21.308) AV5(-2.664,21.328) AV6(-3.337,21.328) AV7(-4.163,21.328) AV8(-4.836,21.328) AV10(-5.661,21.328) AV11(-6.335,21.328) AV12(-7.16,21.328) AV14(-7.833,21.328) AV15(-8.659,21.328) AV16(-9.222,21.003) AV17(-9.86,21.328) AV18(-10.536,21.003) AV19(-11.105,21.328) AV20(-11.751,21.003) AV21(-12.397,21.328) AV22(-12.966,21.003) AV23(-13.642,21.328) AV24(-14.318,21.003) AV25(-14.993,21.328) AV26(-15.669,21.003) AV27(-16.238,21.328) AV28(-16.884,21.003) AV29(-17.531,21.328) AV30(-18.1,21.003) AV31(-18.775,21.328) AV33(-19.4,21.003) AV34(-20.024,21.328) AV35(-20.849,21.328) AV36(-21.599,21.328) AV37(-22.424,21.328) AV39(-23.173,21.328) AV40(-23.999,21.328) AV41(-24.748,21.328) AV42(-25.574,21.328) AV43(-26.323,21.328) AV44(-27.149,21.328) AV46(-27.898,21.328) AV47(-28.723,21.328) AV49(-29.473,21.328) AV50(-30.298,21.328) AV51(-30.98,21.003) AV52(-31.656,21.328) AV53(-32.331,21.003) AV54(-32.9,21.328) AV55(-33.547,21.003) AV56(-34.193,21.328) AV57(-34.762,21.003) AV58(-35.438,21.328) AV59(-36.002,21.003) AV60(-36.566,21.328) AV61(-37.302,21.051) AW4(-1.976,21.968) AW5(-2.626,21.978) AW6(-3.375,21.978) AW7(-4.125,21.978) AW8(-4.874,21.978) AW10(-5.623,21.978) AW11(-6.373,21.978) AW12(-7.122,21.978) AW14(-7.871,21.978) AW15(-8.621,21.978) AW16(-9.222,21.653) AW17(-9.86,21.978) AW18(-10.536,21.653) AW19(-11.211,21.978) AW21(-12.291,21.978) AW22(-12.966,21.653) AW23(-13.642,21.978) AW24(-14.318,21.653) AW25(-14.993,21.978) AW26(-15.669,21.653) AW27(-16.345,21.978) AW29(-17.424,21.978) AW30(-18.1,21.653) AW31(-18.775,21.978) AW33(-19.451,21.653) AW34(-20.024,21.978) AW35(-20.849,21.978) AW36(-21.599,21.978) AW37(-22.424,21.978) AW39(-23.173,21.978) AW40(-23.999,21.978) AW41(-24.748,21.978) AW42(-25.574,21.978) AW43(-26.323,21.978) AW44(-27.149,21.978) AW46(-27.898,21.978) AW47(-28.723,21.978) AW49(-29.473,21.978) AW50(-30.298,21.978) AW51(-30.98,21.653) AW52(-31.656,21.978) AW53(-32.331,21.653) AW54(-33.007,21.978) AW56(-34.087,21.978) AW57(-34.762,21.653) AW58(-35.438,21.978) AW59(-36.002,21.653) AW60(-36.566,21.978) AY6(-3.375,22.628) AY7(-4.125,22.628) AY8(-4.874,22.628) AY10(-5.623,22.628) AY11(-6.373,22.628) AY12(-7.122,22.628) AY14(-7.871,22.628) AY15(-8.621,22.628) AY16(-9.184,22.303) AY17(-9.86,22.628) AY18(-10.536,22.303) AY19(-11.211,22.628) AY21(-12.291,22.628) AY22(-12.966,22.303) AY23(-13.642,22.628) AY24(-14.318,22.303) AY25(-14.993,22.628) AY26(-15.669,22.303) AY27(-16.345,22.628) AY29(-17.424,22.628) AY30(-18.1,22.303) AY31(-18.775,22.628) AY33(-19.451,22.303) AY34(-20.024,22.628) AY35(-20.849,22.628) AY36(-21.599,22.628) AY37(-22.424,22.628) AY39(-23.173,22.628) AY40(-23.999,22.628) AY41(-24.748,22.628) AY42(-25.574,22.628) AY43(-26.323,22.628) AY44(-27.149,22.628) AY46(-27.898,22.628) AY47(-28.723,22.628) AY49(-29.473,22.628) AY50(-30.298,22.628) AY51(-30.98,22.303) AY52(-31.656,22.628) AY53(-32.331,22.303) AY54(-33.007,22.628) AY56(-34.087,22.628) AY57(-34.762,22.303) AY58(-35.438,22.628) B4(-1.922,0.65) B5(-3.138,0.643) B6(-4.119,0.643) B8(-4.891,0.643) B9(-5.716,0.643) B11(-6.697,0.643) B12(-7.469,0.643) B14(-8.294,0.643) B15(-9.275,0.643) B17(-10.047,0.643) B18(-10.872,0.643) B20(-11.853,0.643) B21(-12.272,1.196) B22(-12.625,0.643) B23(-13.451,0.643) B24(-14.023,0.975) B25(-14.714,0.65) B26(-15.277,0.975) B27(-15.84,0.65) B28(-16.531,0.975) B29(-17.221,0.65) B30(-17.785,0.975) B31(-18.348,0.65) B32(-19.038,0.975) B33(-19.729,0.65) B34(-20.292,0.975) B35(-20.855,0.65) B36(-21.546,0.975) B37(-22.236,0.65) B38(-22.8,0.975) B39(-23.363,0.65) B40(-24.053,0.975) B41(-24.744,0.65) B42(-25.307,0.975) B43(-25.87,0.65) B44(-26.561,0.975) B45(-27.251,0.65) B46(-27.815,0.975) B47(-28.378,0.65) B48(-29.068,0.975) B49(-29.759,0.65) B50(-30.322,0.975) B51(-30.885,0.65) B52(-31.576,0.975) B53(-32.266,0.65) B54(-32.83,0.975) B55(-33.393,0.65) B56(-34.083,0.975) B57(-34.774,0.65) B58(-35.337,0.975) B59(-35.9,0.65) B60(-36.665,0.66) C3(-1.302,1.302) C4(-2.118,1.272) C5(-2.772,1.196) C6(-3.776,1.196) C8(-4.538,1.196) C9(-5.351,1.196) C11(-6.354,1.196) C12(-7.116,1.196) C14(-7.929,1.196) C15(-8.932,1.196) C17(-9.694,1.196) C18(-10.507,1.196) C20(-11.51,1.196) C21(-11.891,1.786) C22(-12.678,1.786) C23(-13.085,1.196) C24(-14.051,2.032) C25(-14.714,1.3) C26(-15.277,1.626) C27(-15.84,1.3) C28(-16.558,2.032) C29(-17.221,1.3) C30(-17.785,1.626) C31(-18.348,1.3) C32(-19.066,2.032) C33(-19.729,1.3) C34(-20.292,1.626) C35(-20.855,1.3) C36(-21.573,2.032) C37(-22.236,1.3) C38(-22.8,1.626) C39(-23.363,1.3) C40(-24.081,2.032) C41(-24.744,1.3) C42(-25.307,1.626) C43(-25.87,1.3) C44(-26.588,2.032) C45(-27.251,1.3) C46(-27.815,1.626) C47(-28.378,1.3) C48(-29.07,2.032) C49(-29.759,1.3) C50(-30.322,1.626) C51(-30.885,1.3) C52(-31.578,1.991) C53(-32.266,1.3) C54(-32.83,1.626) C55(-33.393,1.3) C56(-34.085,1.991) C57(-34.774,1.3) C58(-35.337,1.626) C59(-35.9,1.3) C61(-37.003,1.237) D2(-0.65,2.075) D3(-1.3,2.037) D5(-2.678,1.842) D6(-3.369,1.786) D8(-4.157,1.786) D9(-4.944,1.786) D11(-5.852,1.786) D12(-6.735,1.786) D14(-7.522,1.786) D15(-8.43,1.786) D17(-9.313,1.786) D18(-10.1,1.786) D20(-11.008,1.786) D21(-12.235,2.423) D23(-13.377,1.786) D25(-14.714,1.951) D26(-15.277,2.276) D27(-15.84,1.951) D29(-17.221,1.951) D30(-17.785,2.276) D31(-18.348,1.951) D33(-19.729,1.951) D34(-20.292,2.276) D35(-20.855,1.951) D37(-22.236,1.951) D38(-22.8,2.276) D39(-23.363,1.951) D41(-24.744,1.951) D42(-25.307,2.276) D43(-25.87,1.951) D45(-27.251,1.951) D46(-27.815,2.276) D47(-28.378,1.951) D49(-29.759,1.951) D50(-30.322,2.276) D51(-30.885,1.951) D53(-32.266,1.951) D54(-32.83,2.276) D55(-33.393,1.951) D57(-34.774,1.951) D58(-35.337,2.276) D59(-35.9,1.951) D60(-36.678,1.801) D61(-37.328,1.801) D62(-37.978,2.035) E2(-0.65,2.725) E3(-1.3,2.687) E4(-1.951,2.687) E5(-2.602,2.619) E6(-3.554,2.619) E8(-4.507,2.619) E10(-5.459,2.619) E11(-6.412,2.619) E13(-7.364,2.619) E15(-8.317,2.619) E17(-9.269,2.619) E18(-10.222,2.619) E20(-11.174,2.619) E59(-36.027,2.647) E60(-36.678,2.647) E61(-37.328,2.647) E62(-37.978,2.685) F2(-0.65,3.474) F3(-1.3,3.512) F4(-1.951,3.512) F5(-2.602,3.269) F6(-3.554,3.269) F8(-4.507,3.269) F10(-5.459,3.269) F11(-6.412,3.269) F13(-7.364,3.269) F15(-8.317,3.269) F17(-9.269,3.269) F18(-10.222,3.269) F20(-11.174,3.269) F59(-36.027,3.472) F60(-36.678,3.472) F61(-37.328,3.472) F62(-37.978,3.434) F63(-38.628,3.434) G1(0,4.224) G2(-0.65,4.224) G3(-1.3,4.185) G4(-1.951,4.185) G5(-2.602,3.919) G6(-3.554,3.919) G8(-4.507,3.919) G10(-5.459,3.919) G11(-6.412,3.919) G13(-7.364,3.919) G15(-8.317,3.919) G17(-9.269,3.919) G18(-10.222,3.919) G20(-11.174,3.919) H5(-2.602,4.569) H6(-3.554,4.569) H8(-4.507,4.569) H10(-5.459,4.569) H11(-6.412,4.569) H13(-7.364,4.569) H15(-8.317,4.569) H17(-9.269,4.569) H18(-10.222,4.569) H20(-11.174,4.569) H59(-36.027,4.145) H60(-36.678,4.145) H61(-37.328,4.145) H62(-37.978,4.183) H63(-38.628,4.183) J1(0,4.973) J2(-0.65,4.973) J3(-1.3,5.011) J4(-1.951,5.011) J5(-2.627,5.22) J6(-3.567,5.22) J8(-4.507,5.22) J10(-5.459,5.22) J11(-6.412,5.22) J13(-7.364,5.22) J15(-8.317,5.22) J17(-9.269,5.22) J18(-10.222,5.22) J20(-11.174,5.22) J21(-12.095,4.986) J59(-36.027,4.971) J60(-36.678,4.971) J61(-37.328,4.971) J62(-37.978,4.933) J63(-38.628,4.933) K1(0,5.722) K2(-0.65,5.722) K3(-1.3,5.684) K4(-1.951,5.684) K59(-36.027,5.644) K60(-36.678,5.644) K61(-37.328,5.644) K62(-37.978,5.682) K63(-38.628,5.682) L1(0,6.471) L2(-0.65,6.471) L3(-1.3,6.51) L4(-1.951,6.51) L5(-2.637,6.338) L6(-3.287,6.338) L7(-3.937,6.338) L8(-4.587,6.338) L59(-36.027,6.469) L60(-36.678,6.469) L61(-37.328,6.469) L62(-37.978,6.431) L63(-38.628,6.431) N1(0,7.221) N2(-0.65,7.221) N3(-1.3,7.183) N4(-1.951,7.183) N5(-2.637,7.29) N6(-3.287,7.29) N7(-3.937,7.29) N8(-4.587,7.29) N59(-36.027,7.142) N60(-36.678,7.142) N61(-37.328,7.142) N62(-37.978,7.181) N63(-38.628,7.181) P1(0,7.97) P2(-0.65,7.97) P3(-1.3,8.008) P4(-1.951,8.008) P59(-36.027,7.968) P60(-36.678,7.968) P61(-37.328,7.968) P62(-37.978,7.93) P63(-38.628,7.93) R5(-2.637,8.243) R6(-3.287,8.243) R7(-3.937,8.243) R8(-4.587,8.243) T1(0,8.719) T2(-0.65,8.719) T3(-1.3,8.681) T4(-1.951,8.681) T59(-36.027,8.641) T60(-36.678,8.641) T61(-37.328,8.641) T62(-37.978,8.679) T63(-38.628,8.679) U1(0,9.469) U2(-0.65,9.469) U3(-1.3,9.507) U4(-1.951,9.507) U5(-2.637,9.195) U6(-3.287,9.195) U7(-3.937,9.195) U8(-4.587,9.195) U59(-36.027,9.467) U60(-36.678,9.467) U61(-37.328,9.467) U62(-37.978,9.428) U63(-38.628,9.428) V1(0,10.218) V2(-0.65,10.218) V3(-1.3,10.18) V4(-1.951,10.18) V5(-2.637,10.148) V6(-3.287,10.148) V7(-3.937,10.148) V8(-4.587,10.148) V59(-36.027,10.14) V60(-36.678,10.14) V61(-37.328,10.14) V62(-37.978,10.178) V63(-38.628,10.178) Y1(0,10.967) Y2(-0.65,10.967) Y3(-1.3,11.005) Y4(-1.951,11.005) Y5(-2.637,11.1) Y6(-3.287,11.1) Y7(-3.937,11.1) Y8(-4.587,11.1) Y59(-36.027,10.965) Y60(-36.678,10.965) Y61(-37.328,10.965) Y62(-37.978,10.927) Y63(-38.628,10.927)
  round 0.33 smd: AK22(-12.655,16.266) AK23(-13.529,16.266) AK25(-14.504,16.266) AK26(-15.456,16.266) AK28(-16.409,16.266) AK29(-17.311,16.266) AK32(-18.824,16.266) AK33(-19.726,16.266) AK35(-20.729,16.266) AK36(-21.58,16.266) AK38(-22.609,16.266) AK40(-24.106,16.266) AK42(-24.944,16.266) AK43(-25.897,16.266) AK45(-26.874,16.266) AK46(-27.776,16.266) AK48(-28.83,16.266) AK49(-29.732,16.266) AK51(-30.735,16.266) AK52(-31.583,16.266) AK54(-32.61,16.266) AK55(-33.562,16.266) AK57(-34.509,16.266) AK58(-35.408,16.266)
